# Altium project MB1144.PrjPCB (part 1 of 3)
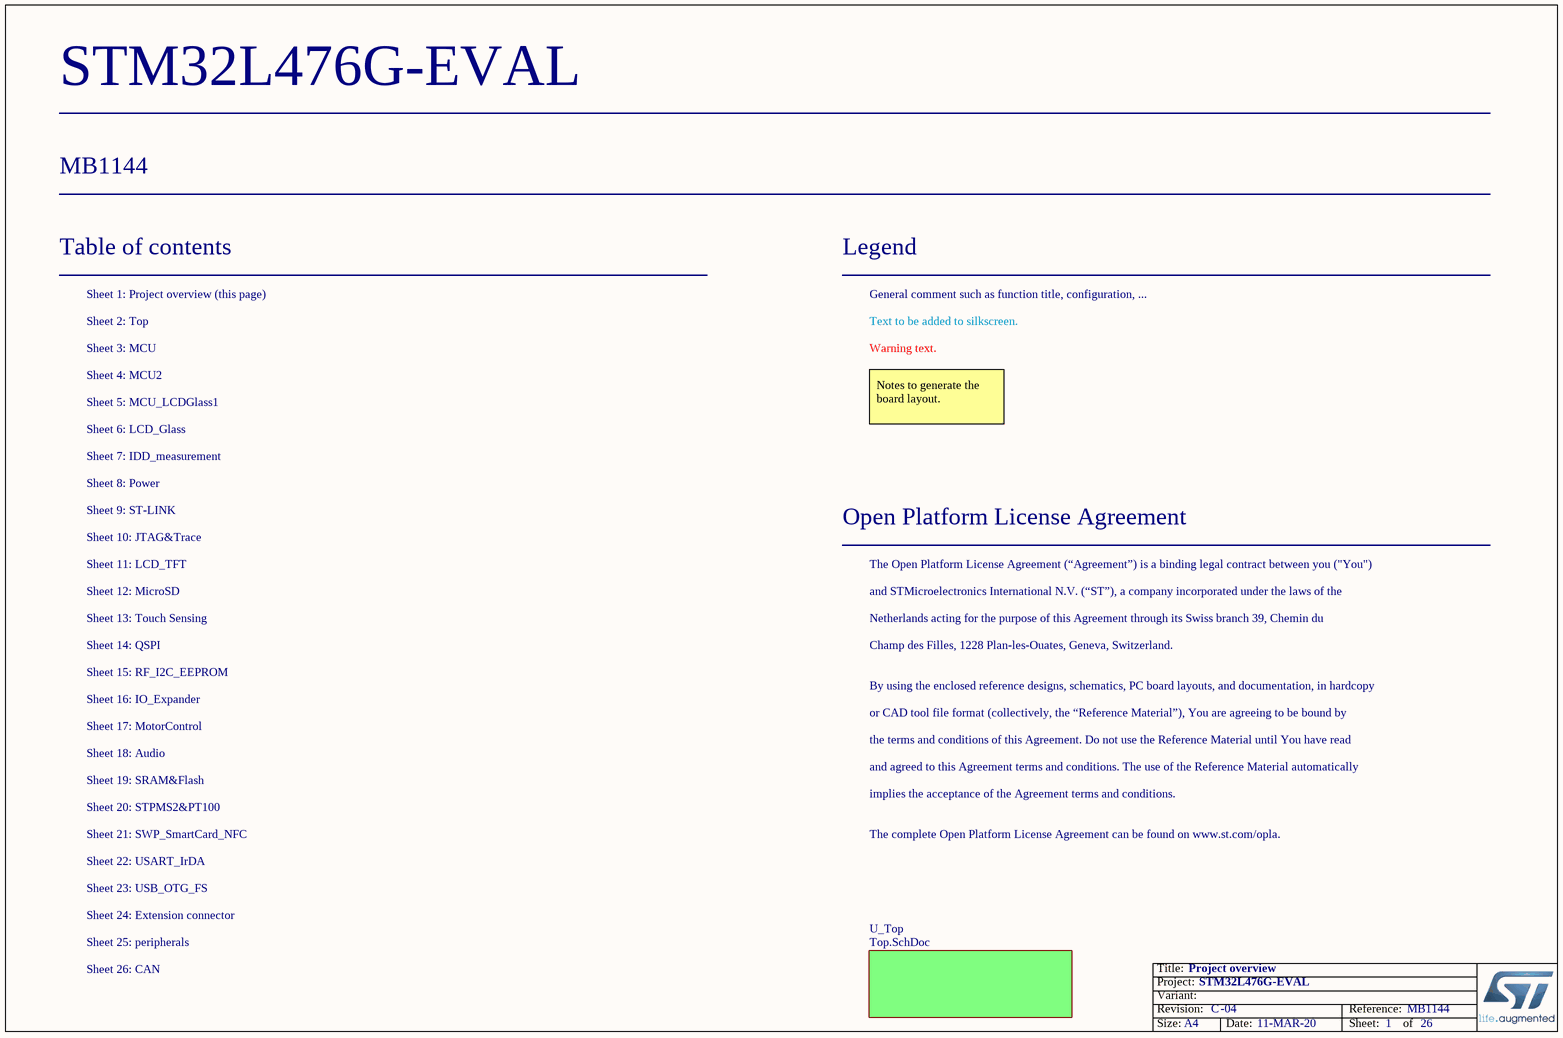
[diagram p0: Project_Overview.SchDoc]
Board_Assembly_Revision: 04; Board_Document_Date: 11-MAR-20; Board_Name: STM32L476G-EVAL; Board_PCB_Revision: C; Board_Reference: MB1144
26 sheets, 601 parts. Net scope: flat (ports and power ports of the same name join across sheets).
Sheets:
  Project_Overview.SchDoc
    U_Top = Top.SchDoc
      U_MCU_LCDGlass_Symbol = MCU_LCDGlass_Symbol.SchDoc
        U_MCU = MCU.SchDoc
        U_LCD_Glass = LCD_Glass.SchDoc
        U_IO_Expandor = IO_Expandor.SchDoc
        U_MCU2 = MCU2.SchDoc
      U_SRAM&Flash = SRAM&Flash.SchDoc
      U_MotorControl = MotorControl.SchDoc
      U_MicroSD = MicroSD.SchDoc
      U_QSPI = QSPI.SchDoc
      U_Extension connector = Extension connector.SCHDOC
      U_JTAG&Trace = JTAG&Trace.SchDoc
      U_ST_LINK = ST_LINK.SCHDOC
      U_USART_IrDA = USART_IrDA.SchDoc
      U_SWP_SmartCard_NFC = SWP_SmartCard_NFC.SchDoc
      U_STPMS2&PT100 = STPMS2&PT100.SchDoc
      U_IDD_measurement = IDD_measurement.SchDoc
      U_USB_OTG_FS = USB_OTG_FS.SchDoc
      U_Touch Sensing = Touch Sensing.SchDoc
      U_CAN = CAN.SchDoc
      U_peripherals = peripherals.SchDoc
      U_Power = Power.SchDoc
      U_Audio = Audio.SchDoc
      U_LCD_TFT = LCD_TFT.SchDoc
      U_RF_I2C_EEPROM = RF_I2C_EEPROM.SchDoc

## Sheet Project_Overview.SchDoc: Project overview
size A4; Date: Not used; ApprovedBy: Not used; CheckedBy: Not used; Author: Not used; CompanyName: STMicroelectronics; DrawnBy: Not used; Engineer: Not used; Organization: Not used; Address1: Not used; Address2: Not used; Address3: Not used; Address4: Not used; DocumentNumber: 1; Revision: Not used; SheetNumber: 1; SheetTotal: 26

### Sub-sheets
U_Top = Top.SchDoc: no entries

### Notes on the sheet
- Table of contents
- Sheet 1: Project overview (this page)
- Legend
- General comment such as function title, configuration, ...
- Sheet 2: Top
- Sheet 3: MCU
- Sheet 4: MCU2
- Text to be added to silkscreen.
- Warning text.
- Sheet 5: MCU_LCDGlass1
- Sheet 6: LCD_Glass
- Notes to generate the board layout.
- Sheet 7: IDD_measurement
- Sheet 8: Power
- Sheet 9: ST-LINK
- Sheet 10: JTAG&Trace
- Sheet 11: LCD_TFT
- Open Platform License Agreement
- The Open Platform License Agreement (“Agreement”) is a binding legal contract between you ("You")
- Sheet 12: MicroSD
- Sheet 13: Touch Sensing
- Sheet 14: QSPI
- and STMicroelectronics International N.V. (“ST”), a company incorporated under the laws of the
- Netherlands acting for the purpose of this Agreement through its Swiss branch 39, Chemin du
- Champ des Filles, 1228 Plan-les-Ouates, Geneva, Switzerland.
- Sheet 15: RF_I2C_EEPROM
- Sheet 16: IO_Expander
- By using the enclosed reference designs, schematics, PC board layouts, and documentation, in hardcopy
- or CAD tool file format (collectively, the “Reference Material”), You are agreeing to be bound by
- Sheet 17: MotorControl
- Sheet 18: Audio
- Sheet 19: SRAM&Flash
- the terms and conditions of this Agreement. Do not use the Reference Material until You have read
- and agreed to this Agreement terms and conditions. The use of the Reference Material automatically
- Sheet 20: STPMS2&PT100
- Sheet 21: SWP_SmartCard_NFC
- implies the acceptance of the Agreement terms and conditions.
- The complete Open Platform License Agreement can be found on www.st.com/opla.
- Sheet 22: USART_IrDA
- Sheet 23: USB_OTG_FS
- Sheet 24: Extension connector
- Sheet 25: peripherals
- Sheet 26: CAN

## Sheet Top.SchDoc: Top schematic
size A3; DocumentNumber: 2; Revision: C-02; SheetNumber: 2; SheetTotal: 26; PageSetup: Record=PageOptions¦CenterHorizontal=True¦CenterVertical=True¦PrintScale=1.01¦XCorrection=1.00¦YCorrection=1.00¦PrintKind=1¦BorderSize=5000000¦LeftOffset=0¦BottomOffset=0¦Orientation=2¦PaperLength=1000¦PaperWidth=1000¦Scale=100¦PaperSource=264¦PrintQuality=600¦MediaType=1¦DitherType=10¦PaperKind=A3¦PrintScaleMode=1; Project: STM32L476G-EVAL
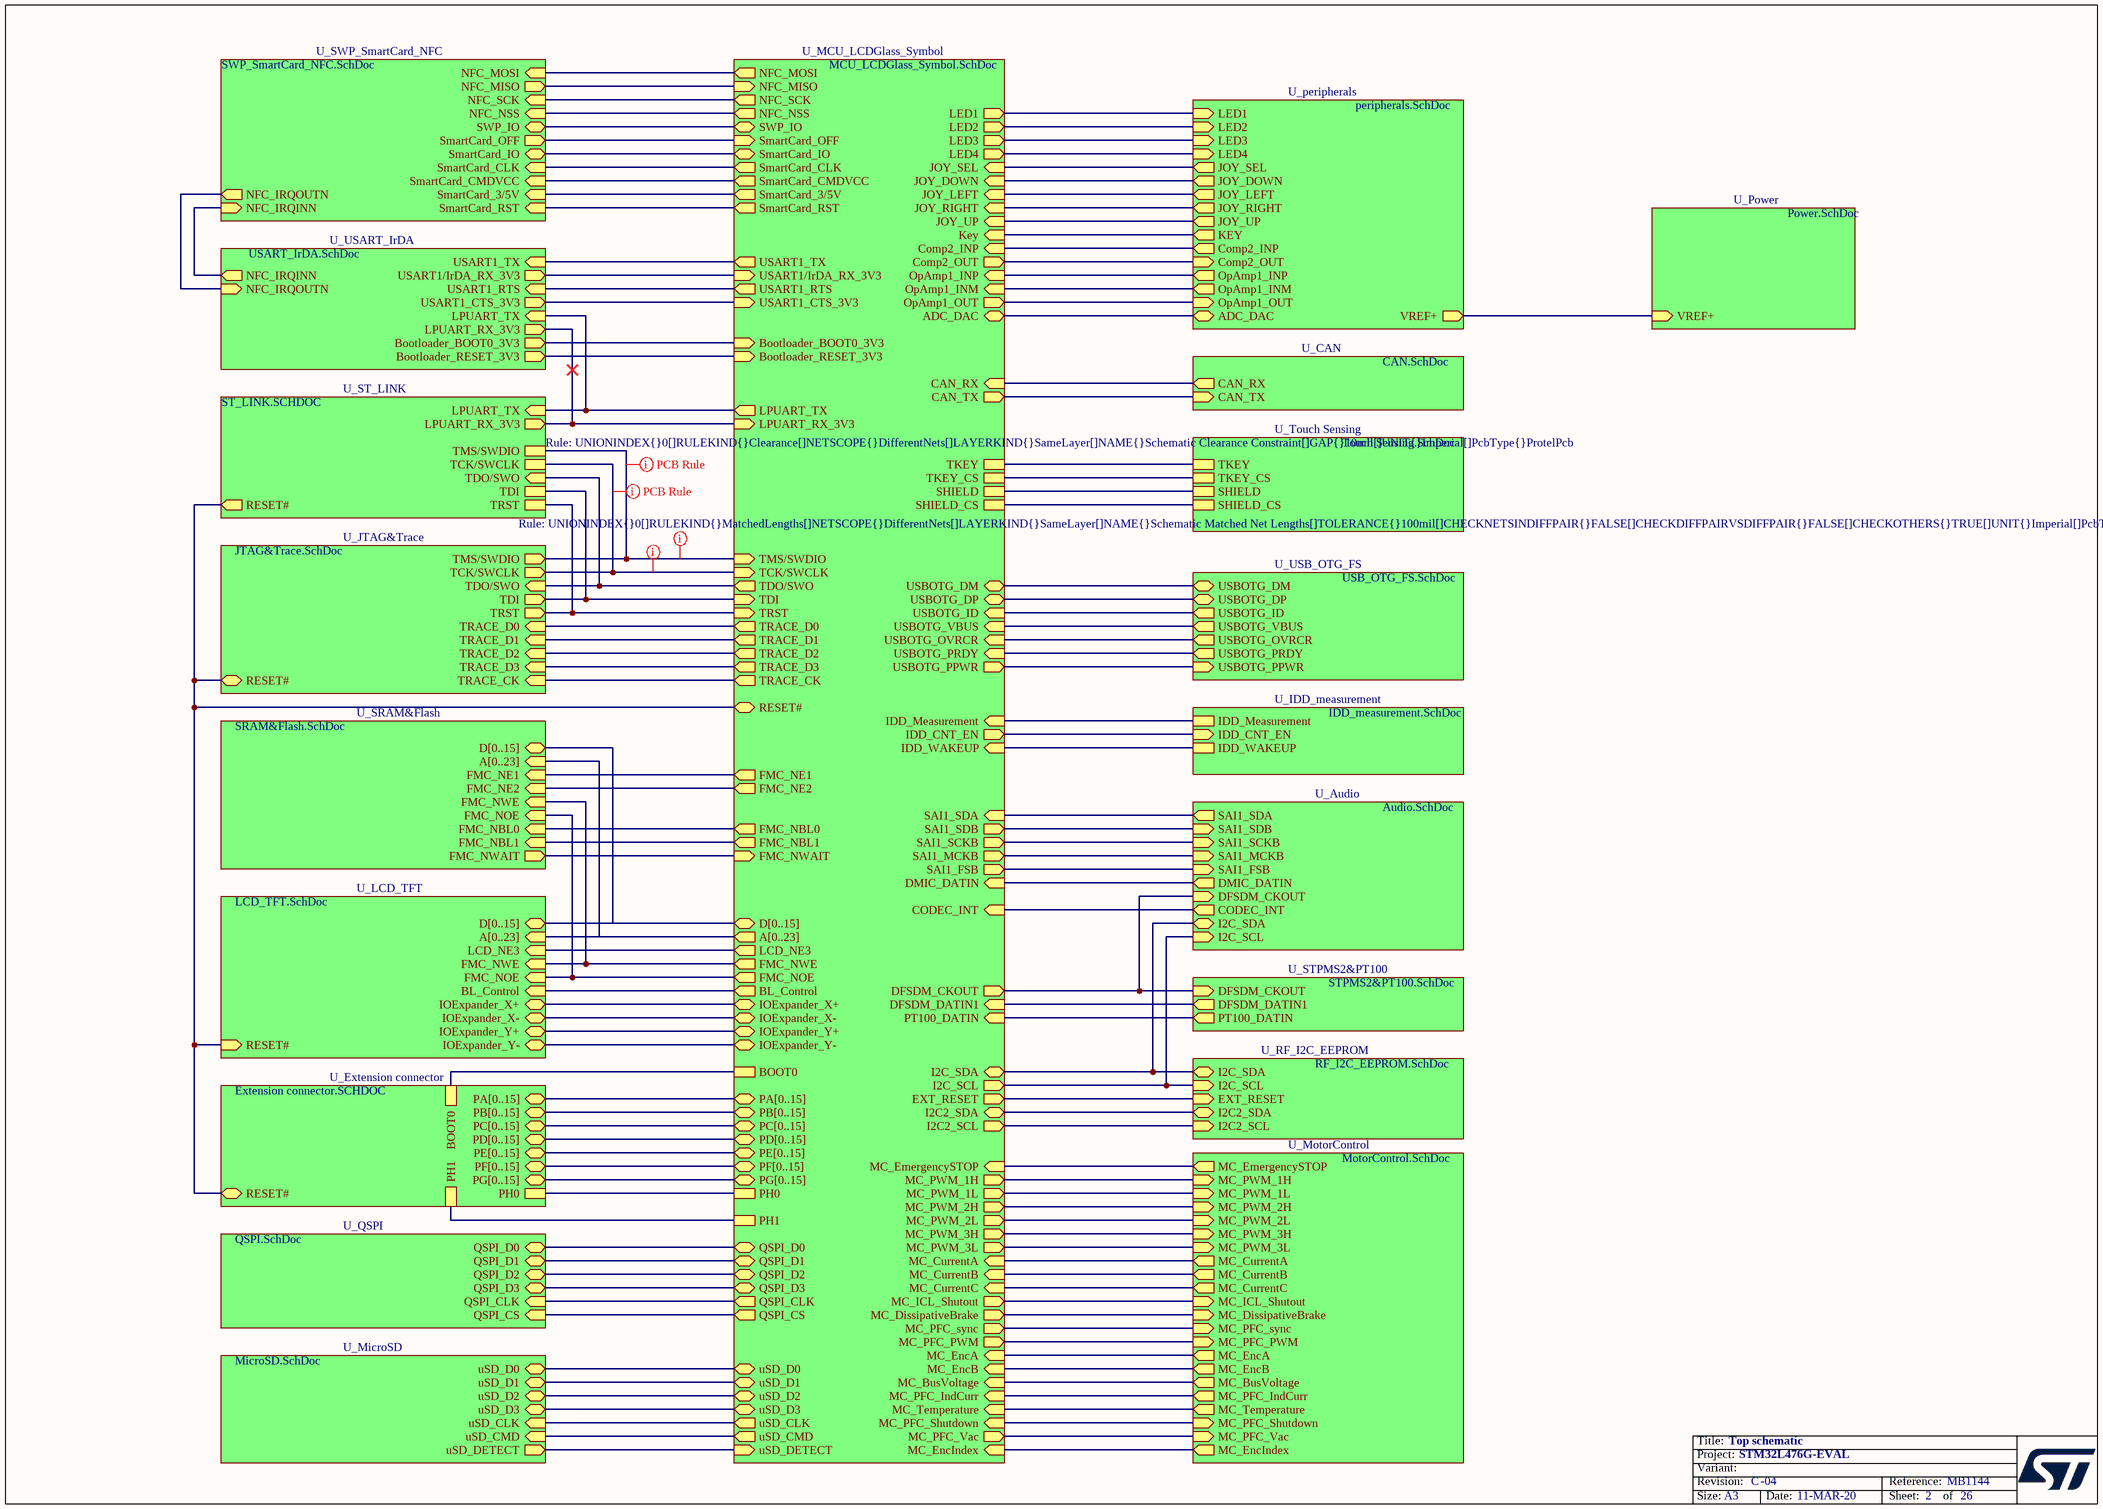
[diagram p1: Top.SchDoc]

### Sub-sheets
U_Audio = Audio.SchDoc: SAI1_SCKB (in), SAI1_FSB (in), SAI1_SDB (in), CODEC_INT (out), I2C_SCL (in), SAI1_MCKB (in), I2C_SDA (bidir), DMIC_DATIN (out), DFSDM_CKOUT (in), SAI1_SDA (out)
U_CAN = CAN.SchDoc: CAN_TX (in), CAN_RX (out)
U_Extension connector = Extension connector.SCHDOC: PA[0..15] (bidir), PB[0..15] (bidir), PC[0..15] (bidir), PD[0..15] (bidir), PE[0..15] (bidir), RESET# (bidir), PF[0..15] (bidir), PG[0..15] (bidir), PH1, PH0, BOOT0
U_IDD_measurement = IDD_measurement.SchDoc: IDD_Measurement, IDD_CNT_EN (in), IDD_WAKEUP
U_JTAG&Trace = JTAG&Trace.SchDoc: TDI (out), RESET# (bidir), TRACE_D3 (in), TRACE_D2 (in), TRACE_D1 (in), TRACE_D0 (in), TRACE_CK (in), TRST (out), TMS/SWDIO (out), TCK/SWCLK (out), TDO/SWO (in)
U_LCD_TFT = LCD_TFT.SchDoc: RESET# (in), FMC_NWE (in), LCD_NE3 (in), FMC_NOE (in), D[0..15] (bidir), A[0..23] (in), IOExpander_Y+ (bidir), IOExpander_Y- (bidir), IOExpander_X+ (bidir), IOExpander_X- (bidir), BL_Control (in)
U_MCU_LCDGlass_Symbol = MCU_LCDGlass_Symbol.SchDoc: FMC_NWAIT (in), FMC_NOE (out), FMC_NWE (out), FMC_NE1 (out), FMC_NE2 (out), LCD_NE3 (out), LED1 (out), LED2 (out), LPUART_TX (out), USART1_TX (out), USART1_RTS (out), TMS/SWDIO (in), TCK/SWCLK (in), TDI (in), TRST (in), Key (in), DFSDM_DATIN1 (in), IDD_Measurement (in), CODEC_INT (in), USBOTG_PRDY (in), USBOTG_OVRCR (in), DMIC_DATIN (in), PT100_DATIN (in), USBOTG_VBUS (in), USBOTG_ID (in), IDD_WAKEUP (in), OpAmp1_INM (in), Comp2_INP (in), TDO/SWO (out), TRACE_D1 (out), TRACE_D2 (out), TRACE_D3 (out), IDD_CNT_EN (out), USBOTG_PPWR (out), TRACE_CK (out), TRACE_D0 (out), SmartCard_CLK (out), OpAmp1_OUT (out), ADC_DAC (bidir), USBOTG_DP (bidir), USBOTG_DM (bidir), SmartCard_IO (bidir), QSPI_D0 (bidir), QSPI_D1 (bidir), QSPI_D2 (bidir), QSPI_D3 (bidir), uSD_D0 (bidir), uSD_D1 (bidir), uSD_D2 (bidir), uSD_D3 (bidir), MC_DissipativeBrake (out), MC_PFC_sync (out), MC_PWM_1H (out), MC_PWM_1L (out), MC_PWM_2H (out), MC_PWM_2L (out), MC_PWM_3H (out), MC_PWM_3L (out), MC_ICL_Shutout (out), MC_PFC_PWM (out), MC_PFC_Vac (out), QSPI_CLK (out), QSPI_CS (out), FMC_NBL0 (out), FMC_NBL1 (out), CAN_TX (out), MC_EncA (in), MC_EncB (in), MC_EncIndex (in), MC_CurrentB (in), MC_CurrentC (in), MC_Temperature (in), MC_PFC_Shutdown (in), CAN_RX (in), uSD_DETECT (in), uSD_CMD (out), uSD_CLK (out), SWP_IO (bidir), IOExpander_X+ (bidir), IOExpander_X- (bidir), IOExpander_Y+ (bidir), IOExpander_Y- (bidir), JOY_SEL (in), JOY_DOWN (in), JOY_LEFT (in), JOY_RIGHT (in), JOY_UP (in), SmartCard_OFF (in), LED4 (out), LED3 (out), SmartCard_RST (out), SmartCard_CMDVCC (out), SmartCard_3/5V (out), D[0..15] (bidir), A[0..23] (out), PA[0..15] (bidir), PB[0..15] (bidir), PC[0..15] (bidir), PD[0..15] (bidir), PE[0..15] (bidir), PF[0..15] (bidir), PG[0..15] (bidir), MC_CurrentA (in), MC_EmergencySTOP (in), MC_BusVoltage (in), MC_PFC_IndCurr (in), RESET# (bidir), DFSDM_CKOUT (out), I2C_SCL (out), I2C_SDA (bidir), PH1, PH0, SHIELD, SAI1_MCKB (out), SAI1_SCKB (out), SAI1_FSB (out), SAI1_SDB (out), SAI1_SDA (in), OpAmp1_INP (in), Comp2_OUT (out), TKEY, TKEY_CS, SHIELD_CS, Bootloader_RESET_3V3 (in), Bootloader_BOOT0_3V3 (in), LPUART_RX_3V3 (in), USART1_CTS_3V3 (in), USART1/IrDA_RX_3V3 (in), BL_Control (out), EXT_RESET (out), BOOT0, NFC_NSS (out), NFC_MOSI (out), NFC_SCK (out), NFC_MISO (in), I2C2_SDA (bidir), I2C2_SCL (out)
U_MicroSD = MicroSD.SchDoc: uSD_CLK (in), uSD_CMD (in), uSD_D0 (bidir), uSD_D1 (bidir), uSD_D2 (bidir), uSD_D3 (bidir), uSD_DETECT (out)
U_MotorControl = MotorControl.SchDoc: MC_EmergencySTOP (out), MC_CurrentA (out), MC_CurrentB (out), MC_CurrentC (out), MC_PFC_sync (in), MC_PWM_3L (in), MC_PWM_2H (in), MC_PWM_2L (in), MC_PWM_1H (in), MC_PWM_1L (in), MC_PWM_3H (in), MC_ICL_Shutout (in), MC_DissipativeBrake (in), MC_PFC_PWM (in), MC_EncA (out), MC_EncB (out), MC_BusVoltage (out), MC_EncIndex (out), MC_PFC_IndCurr (out), MC_Temperature (out), MC_PFC_Shutdown (in), MC_PFC_Vac (in)
U_peripherals = peripherals.SchDoc: ADC_DAC (bidir), LED4 (in), LED3 (in), LED1 (in), LED2 (in), JOY_SEL (out), JOY_DOWN (out), JOY_LEFT (out), JOY_RIGHT (out), JOY_UP (out), KEY (out), VREF+ (out), Comp2_INP (out), OpAmp1_OUT (in), OpAmp1_INM (out), OpAmp1_INP (out), Comp2_OUT (in)
U_Power = Power.SchDoc: VREF+ (in)
U_QSPI = QSPI.SchDoc: QSPI_D0 (bidir), QSPI_D3 (bidir), QSPI_D2 (bidir), QSPI_D1 (bidir), QSPI_CLK (in), QSPI_CS (in)
U_RF_I2C_EEPROM = RF_I2C_EEPROM.SchDoc: I2C_SCL (in), I2C_SDA (bidir), EXT_RESET (in), I2C2_SDA (bidir), I2C2_SCL (in)
U_SRAM&Flash = SRAM&Flash.SchDoc: FMC_NWE (in), FMC_NOE (in), FMC_NWAIT (out), FMC_NBL0 (in), FMC_NBL1 (in), D[0..15] (bidir), A[0..23] (in), FMC_NE1 (in), FMC_NE2 (in)
U_ST_LINK = ST_LINK.SCHDOC: TDO/SWO (in), RESET# (out), TDI, TRST, TMS/SWDIO, TCK/SWCLK, LPUART_RX_3V3 (out), LPUART_TX (in)
U_STPMS2&PT100 = STPMS2&PT100.SchDoc: DFSDM_CKOUT (in), DFSDM_DATIN1 (out), PT100_DATIN (out)
U_SWP_SmartCard_NFC = SWP_SmartCard_NFC.SchDoc: SWP_IO (bidir), SmartCard_3/5V (in), SmartCard_IO (bidir), SmartCard_RST (in), SmartCard_CLK (in), SmartCard_OFF (out), SmartCard_CMDVCC (in), NFC_IRQINN (in), NFC_IRQOUTN (out), NFC_NSS (in), NFC_MOSI (in), NFC_MISO (out), NFC_SCK (in)
U_Touch Sensing = Touch Sensing.SchDoc: SHIELD, SHIELD_CS, TKEY_CS, TKEY
U_USART_IrDA = USART_IrDA.SchDoc: USART1/IrDA_RX_3V3 (out), Bootloader_BOOT0_3V3 (out), Bootloader_RESET_3V3 (out), USART1_CTS_3V3 (out), USART1_TX (in), USART1_RTS (in), LPUART_RX_3V3 (out), LPUART_TX (in), NFC_IRQINN (out), NFC_IRQOUTN (in)
U_USB_OTG_FS = USB_OTG_FS.SchDoc: USBOTG_VBUS (out), USBOTG_PRDY (out), USBOTG_DM (bidir), USBOTG_DP (bidir), USBOTG_OVRCR (out), USBOTG_PPWR (in), USBOTG_ID (out)

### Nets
(unnamed): sheet U_MCU_LCDGlass_Symbol/FMC_NWAIT, sheet U_SRAM&Flash/FMC_NWAIT
(unnamed): sheet U_MCU_LCDGlass_Symbol/FMC_NOE, sheet U_SRAM&Flash/FMC_NOE, sheet U_LCD_TFT/FMC_NOE  [a separate net that carries the same name]
(unnamed): sheet U_MCU_LCDGlass_Symbol/FMC_NWE, sheet U_SRAM&Flash/FMC_NWE, sheet U_LCD_TFT/FMC_NWE  [a separate net that carries the same name]
(unnamed): sheet U_MCU_LCDGlass_Symbol/FMC_NE1, sheet U_SRAM&Flash/FMC_NE1  [a separate net that carries the same name]
(unnamed): sheet U_MCU_LCDGlass_Symbol/FMC_NE2, sheet U_SRAM&Flash/FMC_NE2  [a separate net that carries the same name]
(unnamed): sheet U_MCU_LCDGlass_Symbol/LCD_NE3, sheet U_LCD_TFT/LCD_NE3  [a separate net that carries the same name]
(unnamed): sheet U_MCU_LCDGlass_Symbol/LED1, sheet U_peripherals/LED1  [a separate net that carries the same name]
(unnamed): sheet U_MCU_LCDGlass_Symbol/LED2, sheet U_peripherals/LED2  [a separate net that carries the same name]
(unnamed): sheet U_MCU_LCDGlass_Symbol/LPUART_TX, sheet U_ST_LINK/LPUART_TX, sheet U_USART_IrDA/LPUART_TX  [a separate net that carries the same name]
(unnamed): sheet U_MCU_LCDGlass_Symbol/USART1_TX, sheet U_USART_IrDA/USART1_TX  [a separate net that carries the same name]
(unnamed): sheet U_MCU_LCDGlass_Symbol/USART1_RTS, sheet U_USART_IrDA/USART1_RTS  [a separate net that carries the same name]
(unnamed): sheet U_MCU_LCDGlass_Symbol/TMS/SWDIO, sheet U_JTAG&Trace/TMS/SWDIO, sheet U_ST_LINK/TMS/SWDIO  [a separate net that carries the same name]
(unnamed): sheet U_MCU_LCDGlass_Symbol/TCK/SWCLK, sheet U_JTAG&Trace/TCK/SWCLK, sheet U_ST_LINK/TCK/SWCLK  [a separate net that carries the same name]
(unnamed): sheet U_MCU_LCDGlass_Symbol/TDI, sheet U_JTAG&Trace/TDI, sheet U_ST_LINK/TDI  [a separate net that carries the same name]
(unnamed): sheet U_MCU_LCDGlass_Symbol/TRST, sheet U_JTAG&Trace/TRST, sheet U_ST_LINK/TRST  [a separate net that carries the same name]
(unnamed): sheet U_MCU_LCDGlass_Symbol/Key, sheet U_peripherals/KEY  [a separate net that carries the same name]
(unnamed): sheet U_MCU_LCDGlass_Symbol/DFSDM_DATIN1, sheet U_STPMS2&PT100/DFSDM_DATIN1  [a separate net that carries the same name]
(unnamed): sheet U_MCU_LCDGlass_Symbol/IDD_Measurement, sheet U_IDD_measurement/IDD_Measurement  [a separate net that carries the same name]
(unnamed): sheet U_MCU_LCDGlass_Symbol/CODEC_INT, sheet U_Audio/CODEC_INT  [a separate net that carries the same name]
(unnamed): sheet U_MCU_LCDGlass_Symbol/USBOTG_PRDY, sheet U_USB_OTG_FS/USBOTG_PRDY  [a separate net that carries the same name]
(unnamed): sheet U_MCU_LCDGlass_Symbol/USBOTG_OVRCR, sheet U_USB_OTG_FS/USBOTG_OVRCR  [a separate net that carries the same name]
(unnamed): sheet U_MCU_LCDGlass_Symbol/DMIC_DATIN, sheet U_Audio/DMIC_DATIN  [a separate net that carries the same name]
(unnamed): sheet U_MCU_LCDGlass_Symbol/PT100_DATIN, sheet U_STPMS2&PT100/PT100_DATIN  [a separate net that carries the same name]
(unnamed): sheet U_MCU_LCDGlass_Symbol/USBOTG_VBUS, sheet U_USB_OTG_FS/USBOTG_VBUS  [a separate net that carries the same name]
(unnamed): sheet U_MCU_LCDGlass_Symbol/USBOTG_ID, sheet U_USB_OTG_FS/USBOTG_ID  [a separate net that carries the same name]
(unnamed): sheet U_MCU_LCDGlass_Symbol/IDD_WAKEUP, sheet U_IDD_measurement/IDD_WAKEUP  [a separate net that carries the same name]
(unnamed): sheet U_MCU_LCDGlass_Symbol/OpAmp1_INM, sheet U_peripherals/OpAmp1_INM  [a separate net that carries the same name]
(unnamed): sheet U_MCU_LCDGlass_Symbol/Comp2_INP, sheet U_peripherals/Comp2_INP  [a separate net that carries the same name]
(unnamed): sheet U_MCU_LCDGlass_Symbol/TDO/SWO, sheet U_JTAG&Trace/TDO/SWO, sheet U_ST_LINK/TDO/SWO  [a separate net that carries the same name]
(unnamed): sheet U_MCU_LCDGlass_Symbol/TRACE_D1, sheet U_JTAG&Trace/TRACE_D1  [a separate net that carries the same name]
(unnamed): sheet U_MCU_LCDGlass_Symbol/TRACE_D2, sheet U_JTAG&Trace/TRACE_D2  [a separate net that carries the same name]
(unnamed): sheet U_MCU_LCDGlass_Symbol/TRACE_D3, sheet U_JTAG&Trace/TRACE_D3  [a separate net that carries the same name]
(unnamed): sheet U_MCU_LCDGlass_Symbol/IDD_CNT_EN, sheet U_IDD_measurement/IDD_CNT_EN  [a separate net that carries the same name]
(unnamed): sheet U_MCU_LCDGlass_Symbol/USBOTG_PPWR, sheet U_USB_OTG_FS/USBOTG_PPWR  [a separate net that carries the same name]
(unnamed): sheet U_MCU_LCDGlass_Symbol/TRACE_CK, sheet U_JTAG&Trace/TRACE_CK  [a separate net that carries the same name]
(unnamed): sheet U_MCU_LCDGlass_Symbol/TRACE_D0, sheet U_JTAG&Trace/TRACE_D0  [a separate net that carries the same name]
(unnamed): sheet U_MCU_LCDGlass_Symbol/SmartCard_CLK, sheet U_SWP_SmartCard_NFC/SmartCard_CLK  [a separate net that carries the same name]
(unnamed): sheet U_MCU_LCDGlass_Symbol/OpAmp1_OUT, sheet U_peripherals/OpAmp1_OUT  [a separate net that carries the same name]
(unnamed): sheet U_MCU_LCDGlass_Symbol/ADC_DAC, sheet U_peripherals/ADC_DAC  [a separate net that carries the same name]
(unnamed): sheet U_MCU_LCDGlass_Symbol/USBOTG_DP, sheet U_USB_OTG_FS/USBOTG_DP  [a separate net that carries the same name]
(unnamed): sheet U_MCU_LCDGlass_Symbol/USBOTG_DM, sheet U_USB_OTG_FS/USBOTG_DM  [a separate net that carries the same name]
(unnamed): sheet U_MCU_LCDGlass_Symbol/SmartCard_IO, sheet U_SWP_SmartCard_NFC/SmartCard_IO  [a separate net that carries the same name]
(unnamed): sheet U_MCU_LCDGlass_Symbol/QSPI_D0, sheet U_QSPI/QSPI_D0  [a separate net that carries the same name]
(unnamed): sheet U_MCU_LCDGlass_Symbol/QSPI_D1, sheet U_QSPI/QSPI_D1  [a separate net that carries the same name]
(unnamed): sheet U_MCU_LCDGlass_Symbol/QSPI_D2, sheet U_QSPI/QSPI_D2  [a separate net that carries the same name]
(unnamed): sheet U_MCU_LCDGlass_Symbol/QSPI_D3, sheet U_QSPI/QSPI_D3  [a separate net that carries the same name]
(unnamed): sheet U_MCU_LCDGlass_Symbol/uSD_D0, sheet U_MicroSD/uSD_D0  [a separate net that carries the same name]
(unnamed): sheet U_MCU_LCDGlass_Symbol/uSD_D1, sheet U_MicroSD/uSD_D1  [a separate net that carries the same name]
(unnamed): sheet U_MCU_LCDGlass_Symbol/uSD_D2, sheet U_MicroSD/uSD_D2  [a separate net that carries the same name]
(unnamed): sheet U_MCU_LCDGlass_Symbol/uSD_D3, sheet U_MicroSD/uSD_D3  [a separate net that carries the same name]
(unnamed): sheet U_MCU_LCDGlass_Symbol/MC_DissipativeBrake, sheet U_MotorControl/MC_DissipativeBrake  [a separate net that carries the same name]
(unnamed): sheet U_MCU_LCDGlass_Symbol/MC_PFC_sync, sheet U_MotorControl/MC_PFC_sync  [a separate net that carries the same name]
(unnamed): sheet U_MCU_LCDGlass_Symbol/MC_PWM_1H, sheet U_MotorControl/MC_PWM_1H  [a separate net that carries the same name]
(unnamed): sheet U_MCU_LCDGlass_Symbol/MC_PWM_1L, sheet U_MotorControl/MC_PWM_1L  [a separate net that carries the same name]
(unnamed): sheet U_MCU_LCDGlass_Symbol/MC_PWM_2H, sheet U_MotorControl/MC_PWM_2H  [a separate net that carries the same name]
(unnamed): sheet U_MCU_LCDGlass_Symbol/MC_PWM_2L, sheet U_MotorControl/MC_PWM_2L  [a separate net that carries the same name]
(unnamed): sheet U_MCU_LCDGlass_Symbol/MC_PWM_3H, sheet U_MotorControl/MC_PWM_3H  [a separate net that carries the same name]
(unnamed): sheet U_MCU_LCDGlass_Symbol/MC_PWM_3L, sheet U_MotorControl/MC_PWM_3L  [a separate net that carries the same name]
(unnamed): sheet U_MCU_LCDGlass_Symbol/MC_ICL_Shutout, sheet U_MotorControl/MC_ICL_Shutout  [a separate net that carries the same name]
(unnamed): sheet U_MCU_LCDGlass_Symbol/MC_PFC_PWM, sheet U_MotorControl/MC_PFC_PWM  [a separate net that carries the same name]
(unnamed): sheet U_MCU_LCDGlass_Symbol/MC_PFC_Vac, sheet U_MotorControl/MC_PFC_Vac  [a separate net that carries the same name]
(unnamed): sheet U_MCU_LCDGlass_Symbol/QSPI_CLK, sheet U_QSPI/QSPI_CLK  [a separate net that carries the same name]
(unnamed): sheet U_MCU_LCDGlass_Symbol/QSPI_CS, sheet U_QSPI/QSPI_CS  [a separate net that carries the same name]
(unnamed): sheet U_MCU_LCDGlass_Symbol/FMC_NBL0, sheet U_SRAM&Flash/FMC_NBL0  [a separate net that carries the same name]
(unnamed): sheet U_MCU_LCDGlass_Symbol/FMC_NBL1, sheet U_SRAM&Flash/FMC_NBL1  [a separate net that carries the same name]
(unnamed): sheet U_MCU_LCDGlass_Symbol/CAN_TX, sheet U_CAN/CAN_TX  [a separate net that carries the same name]
(unnamed): sheet U_MCU_LCDGlass_Symbol/MC_EncA, sheet U_MotorControl/MC_EncA  [a separate net that carries the same name]
(unnamed): sheet U_MCU_LCDGlass_Symbol/MC_EncB, sheet U_MotorControl/MC_EncB  [a separate net that carries the same name]
(unnamed): sheet U_MCU_LCDGlass_Symbol/MC_EncIndex, sheet U_MotorControl/MC_EncIndex  [a separate net that carries the same name]
(unnamed): sheet U_MCU_LCDGlass_Symbol/MC_CurrentB, sheet U_MotorControl/MC_CurrentB  [a separate net that carries the same name]
(unnamed): sheet U_MCU_LCDGlass_Symbol/MC_CurrentC, sheet U_MotorControl/MC_CurrentC  [a separate net that carries the same name]
(unnamed): sheet U_MCU_LCDGlass_Symbol/MC_Temperature, sheet U_MotorControl/MC_Temperature  [a separate net that carries the same name]
(unnamed): sheet U_MCU_LCDGlass_Symbol/MC_PFC_Shutdown, sheet U_MotorControl/MC_PFC_Shutdown  [a separate net that carries the same name]
(unnamed): sheet U_MCU_LCDGlass_Symbol/CAN_RX, sheet U_CAN/CAN_RX  [a separate net that carries the same name]
(unnamed): sheet U_MCU_LCDGlass_Symbol/uSD_DETECT, sheet U_MicroSD/uSD_DETECT  [a separate net that carries the same name]
(unnamed): sheet U_MCU_LCDGlass_Symbol/uSD_CMD, sheet U_MicroSD/uSD_CMD  [a separate net that carries the same name]
(unnamed): sheet U_MCU_LCDGlass_Symbol/uSD_CLK, sheet U_MicroSD/uSD_CLK  [a separate net that carries the same name]
(unnamed): sheet U_MCU_LCDGlass_Symbol/SWP_IO, sheet U_SWP_SmartCard_NFC/SWP_IO  [a separate net that carries the same name]
(unnamed): sheet U_MCU_LCDGlass_Symbol/IOExpander_X+, sheet U_LCD_TFT/IOExpander_X+  [a separate net that carries the same name]
(unnamed): sheet U_MCU_LCDGlass_Symbol/IOExpander_X-, sheet U_LCD_TFT/IOExpander_X-  [a separate net that carries the same name]
(unnamed): sheet U_MCU_LCDGlass_Symbol/IOExpander_Y+, sheet U_LCD_TFT/IOExpander_Y+  [a separate net that carries the same name]
(unnamed): sheet U_MCU_LCDGlass_Symbol/IOExpander_Y-, sheet U_LCD_TFT/IOExpander_Y-  [a separate net that carries the same name]
(unnamed): sheet U_MCU_LCDGlass_Symbol/JOY_SEL, sheet U_peripherals/JOY_SEL  [a separate net that carries the same name]
(unnamed): sheet U_MCU_LCDGlass_Symbol/JOY_DOWN, sheet U_peripherals/JOY_DOWN  [a separate net that carries the same name]
(unnamed): sheet U_MCU_LCDGlass_Symbol/JOY_LEFT, sheet U_peripherals/JOY_LEFT  [a separate net that carries the same name]
(unnamed): sheet U_MCU_LCDGlass_Symbol/JOY_RIGHT, sheet U_peripherals/JOY_RIGHT  [a separate net that carries the same name]
(unnamed): sheet U_MCU_LCDGlass_Symbol/JOY_UP, sheet U_peripherals/JOY_UP  [a separate net that carries the same name]
(unnamed): sheet U_MCU_LCDGlass_Symbol/SmartCard_OFF, sheet U_SWP_SmartCard_NFC/SmartCard_OFF  [a separate net that carries the same name]
(unnamed): sheet U_MCU_LCDGlass_Symbol/LED4, sheet U_peripherals/LED4  [a separate net that carries the same name]
(unnamed): sheet U_MCU_LCDGlass_Symbol/LED3, sheet U_peripherals/LED3  [a separate net that carries the same name]
(unnamed): sheet U_MCU_LCDGlass_Symbol/SmartCard_RST, sheet U_SWP_SmartCard_NFC/SmartCard_RST  [a separate net that carries the same name]
(unnamed): sheet U_MCU_LCDGlass_Symbol/SmartCard_CMDVCC, sheet U_SWP_SmartCard_NFC/SmartCard_CMDVCC  [a separate net that carries the same name]
(unnamed): sheet U_MCU_LCDGlass_Symbol/SmartCard_3/5V, sheet U_SWP_SmartCard_NFC/SmartCard_3/5V  [a separate net that carries the same name]
(unnamed): sheet U_MCU_LCDGlass_Symbol/MC_CurrentA, sheet U_MotorControl/MC_CurrentA  [a separate net that carries the same name]
(unnamed): sheet U_MCU_LCDGlass_Symbol/MC_EmergencySTOP, sheet U_MotorControl/MC_EmergencySTOP  [a separate net that carries the same name]
(unnamed): sheet U_MCU_LCDGlass_Symbol/MC_BusVoltage, sheet U_MotorControl/MC_BusVoltage  [a separate net that carries the same name]
(unnamed): sheet U_MCU_LCDGlass_Symbol/MC_PFC_IndCurr, sheet U_MotorControl/MC_PFC_IndCurr  [a separate net that carries the same name]
(unnamed): sheet U_MCU_LCDGlass_Symbol/RESET#, sheet U_Extension connector/RESET#, sheet U_JTAG&Trace/RESET#, sheet U_ST_LINK/RESET#, sheet U_LCD_TFT/RESET#  [a separate net that carries the same name]
(unnamed): sheet U_MCU_LCDGlass_Symbol/DFSDM_CKOUT, sheet U_STPMS2&PT100/DFSDM_CKOUT, sheet U_Audio/DFSDM_CKOUT  [a separate net that carries the same name]
(unnamed): sheet U_MCU_LCDGlass_Symbol/I2C_SCL, sheet U_Audio/I2C_SCL, sheet U_RF_I2C_EEPROM/I2C_SCL  [a separate net that carries the same name]
(unnamed): sheet U_MCU_LCDGlass_Symbol/I2C_SDA, sheet U_Audio/I2C_SDA, sheet U_RF_I2C_EEPROM/I2C_SDA  [a separate net that carries the same name]
(unnamed): sheet U_MCU_LCDGlass_Symbol/PH1, sheet U_Extension connector/PH1  [a separate net that carries the same name]
(unnamed): sheet U_MCU_LCDGlass_Symbol/PH0, sheet U_Extension connector/PH0  [a separate net that carries the same name]
(unnamed): sheet U_MCU_LCDGlass_Symbol/SHIELD, sheet U_Touch Sensing/SHIELD  [a separate net that carries the same name]
(unnamed): sheet U_MCU_LCDGlass_Symbol/SAI1_MCKB, sheet U_Audio/SAI1_MCKB  [a separate net that carries the same name]
(unnamed): sheet U_MCU_LCDGlass_Symbol/SAI1_SCKB, sheet U_Audio/SAI1_SCKB  [a separate net that carries the same name]
(unnamed): sheet U_MCU_LCDGlass_Symbol/SAI1_FSB, sheet U_Audio/SAI1_FSB  [a separate net that carries the same name]
(unnamed): sheet U_MCU_LCDGlass_Symbol/SAI1_SDB, sheet U_Audio/SAI1_SDB  [a separate net that carries the same name]
(unnamed): sheet U_MCU_LCDGlass_Symbol/SAI1_SDA, sheet U_Audio/SAI1_SDA  [a separate net that carries the same name]
(unnamed): sheet U_MCU_LCDGlass_Symbol/OpAmp1_INP, sheet U_peripherals/OpAmp1_INP  [a separate net that carries the same name]
(unnamed): sheet U_MCU_LCDGlass_Symbol/Comp2_OUT, sheet U_peripherals/Comp2_OUT  [a separate net that carries the same name]
(unnamed): sheet U_MCU_LCDGlass_Symbol/TKEY, sheet U_Touch Sensing/TKEY  [a separate net that carries the same name]
(unnamed): sheet U_MCU_LCDGlass_Symbol/TKEY_CS, sheet U_Touch Sensing/TKEY_CS  [a separate net that carries the same name]
(unnamed): sheet U_MCU_LCDGlass_Symbol/SHIELD_CS, sheet U_Touch Sensing/SHIELD_CS  [a separate net that carries the same name]
(unnamed): sheet U_MCU_LCDGlass_Symbol/Bootloader_RESET_3V3, sheet U_USART_IrDA/Bootloader_RESET_3V3  [a separate net that carries the same name]
(unnamed): sheet U_MCU_LCDGlass_Symbol/Bootloader_BOOT0_3V3, sheet U_USART_IrDA/Bootloader_BOOT0_3V3  [a separate net that carries the same name]
(unnamed): sheet U_MCU_LCDGlass_Symbol/LPUART_RX_3V3, sheet U_ST_LINK/LPUART_RX_3V3, sheet U_USART_IrDA/LPUART_RX_3V3  [a separate net that carries the same name]
(unnamed): sheet U_MCU_LCDGlass_Symbol/USART1_CTS_3V3, sheet U_USART_IrDA/USART1_CTS_3V3  [a separate net that carries the same name]
(unnamed): sheet U_MCU_LCDGlass_Symbol/USART1/IrDA_RX_3V3, sheet U_USART_IrDA/USART1/IrDA_RX_3V3  [a separate net that carries the same name]
(unnamed): sheet U_MCU_LCDGlass_Symbol/BL_Control, sheet U_LCD_TFT/BL_Control  [a separate net that carries the same name]
(unnamed): sheet U_MCU_LCDGlass_Symbol/EXT_RESET, sheet U_RF_I2C_EEPROM/EXT_RESET  [a separate net that carries the same name]
(unnamed): sheet U_MCU_LCDGlass_Symbol/BOOT0, sheet U_Extension connector/BOOT0  [a separate net that carries the same name]
(unnamed): sheet U_MCU_LCDGlass_Symbol/NFC_NSS, sheet U_SWP_SmartCard_NFC/NFC_NSS  [a separate net that carries the same name]
(unnamed): sheet U_MCU_LCDGlass_Symbol/NFC_MOSI, sheet U_SWP_SmartCard_NFC/NFC_MOSI  [a separate net that carries the same name]
(unnamed): sheet U_MCU_LCDGlass_Symbol/NFC_SCK, sheet U_SWP_SmartCard_NFC/NFC_SCK  [a separate net that carries the same name]
(unnamed): sheet U_MCU_LCDGlass_Symbol/NFC_MISO, sheet U_SWP_SmartCard_NFC/NFC_MISO  [a separate net that carries the same name]
(unnamed): sheet U_MCU_LCDGlass_Symbol/I2C2_SDA, sheet U_RF_I2C_EEPROM/I2C2_SDA  [a separate net that carries the same name]
(unnamed): sheet U_MCU_LCDGlass_Symbol/I2C2_SCL, sheet U_RF_I2C_EEPROM/I2C2_SCL  [a separate net that carries the same name]
(unnamed): sheet U_USART_IrDA/NFC_IRQINN, sheet U_SWP_SmartCard_NFC/NFC_IRQINN  [a separate net that carries the same name]
(unnamed): sheet U_USART_IrDA/NFC_IRQOUTN, sheet U_SWP_SmartCard_NFC/NFC_IRQOUTN  [a separate net that carries the same name]
(unnamed): sheet U_peripherals/VREF+, sheet U_Power/VREF+  [a separate net that carries the same name]

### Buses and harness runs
bus sheet U_Extension connector/PA[0..15] = sheet U_MCU_LCDGlass_Symbol/PA[0..15]
bus sheet U_Extension connector/PB[0..15] = sheet U_MCU_LCDGlass_Symbol/PB[0..15]
bus sheet U_Extension connector/PC[0..15] = sheet U_MCU_LCDGlass_Symbol/PC[0..15]
bus sheet U_Extension connector/PD[0..15] = sheet U_MCU_LCDGlass_Symbol/PD[0..15]
bus sheet U_Extension connector/PE[0..15] = sheet U_MCU_LCDGlass_Symbol/PE[0..15]
bus sheet U_Extension connector/PF[0..15] = sheet U_MCU_LCDGlass_Symbol/PF[0..15]
bus sheet U_Extension connector/PG[0..15] = sheet U_MCU_LCDGlass_Symbol/PG[0..15]
bus sheet U_LCD_TFT/A[0..23] = sheet U_MCU_LCDGlass_Symbol/A[0..23] = sheet U_SRAM&Flash/A[0..23]
bus sheet U_LCD_TFT/D[0..15] = sheet U_MCU_LCDGlass_Symbol/D[0..15] = sheet U_SRAM&Flash/D[0..15]

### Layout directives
rule Matched Net Lengths [Tolerance = 100mil]: (no net found under the mark)
rule Clearance Constraint [Clearance = 10mil]: (no net found under the mark)

## Sheet MCU_LCDGlass_Symbol.SchDoc: MCU_LCDGlassl
size A3; DocumentNumber: 5; Revision: C-02; SheetNumber: 5; SheetTotal: 26; PageSetup: Record=PageOptions¦CenterHorizontal=True¦CenterVertical=True¦PrintScale=1.01¦XCorrection=1.00¦YCorrection=1.00¦PrintKind=1¦BorderSize=5000000¦LeftOffset=0¦BottomOffset=0¦Orientation=2¦PaperLength=1000¦PaperWidth=1000¦Scale=100¦PaperSource=264¦PrintQuality=600¦MediaType=1¦DitherType=10¦PaperKind=A3¦PrintScaleMode=1; Project: STM32L476G-EVAL
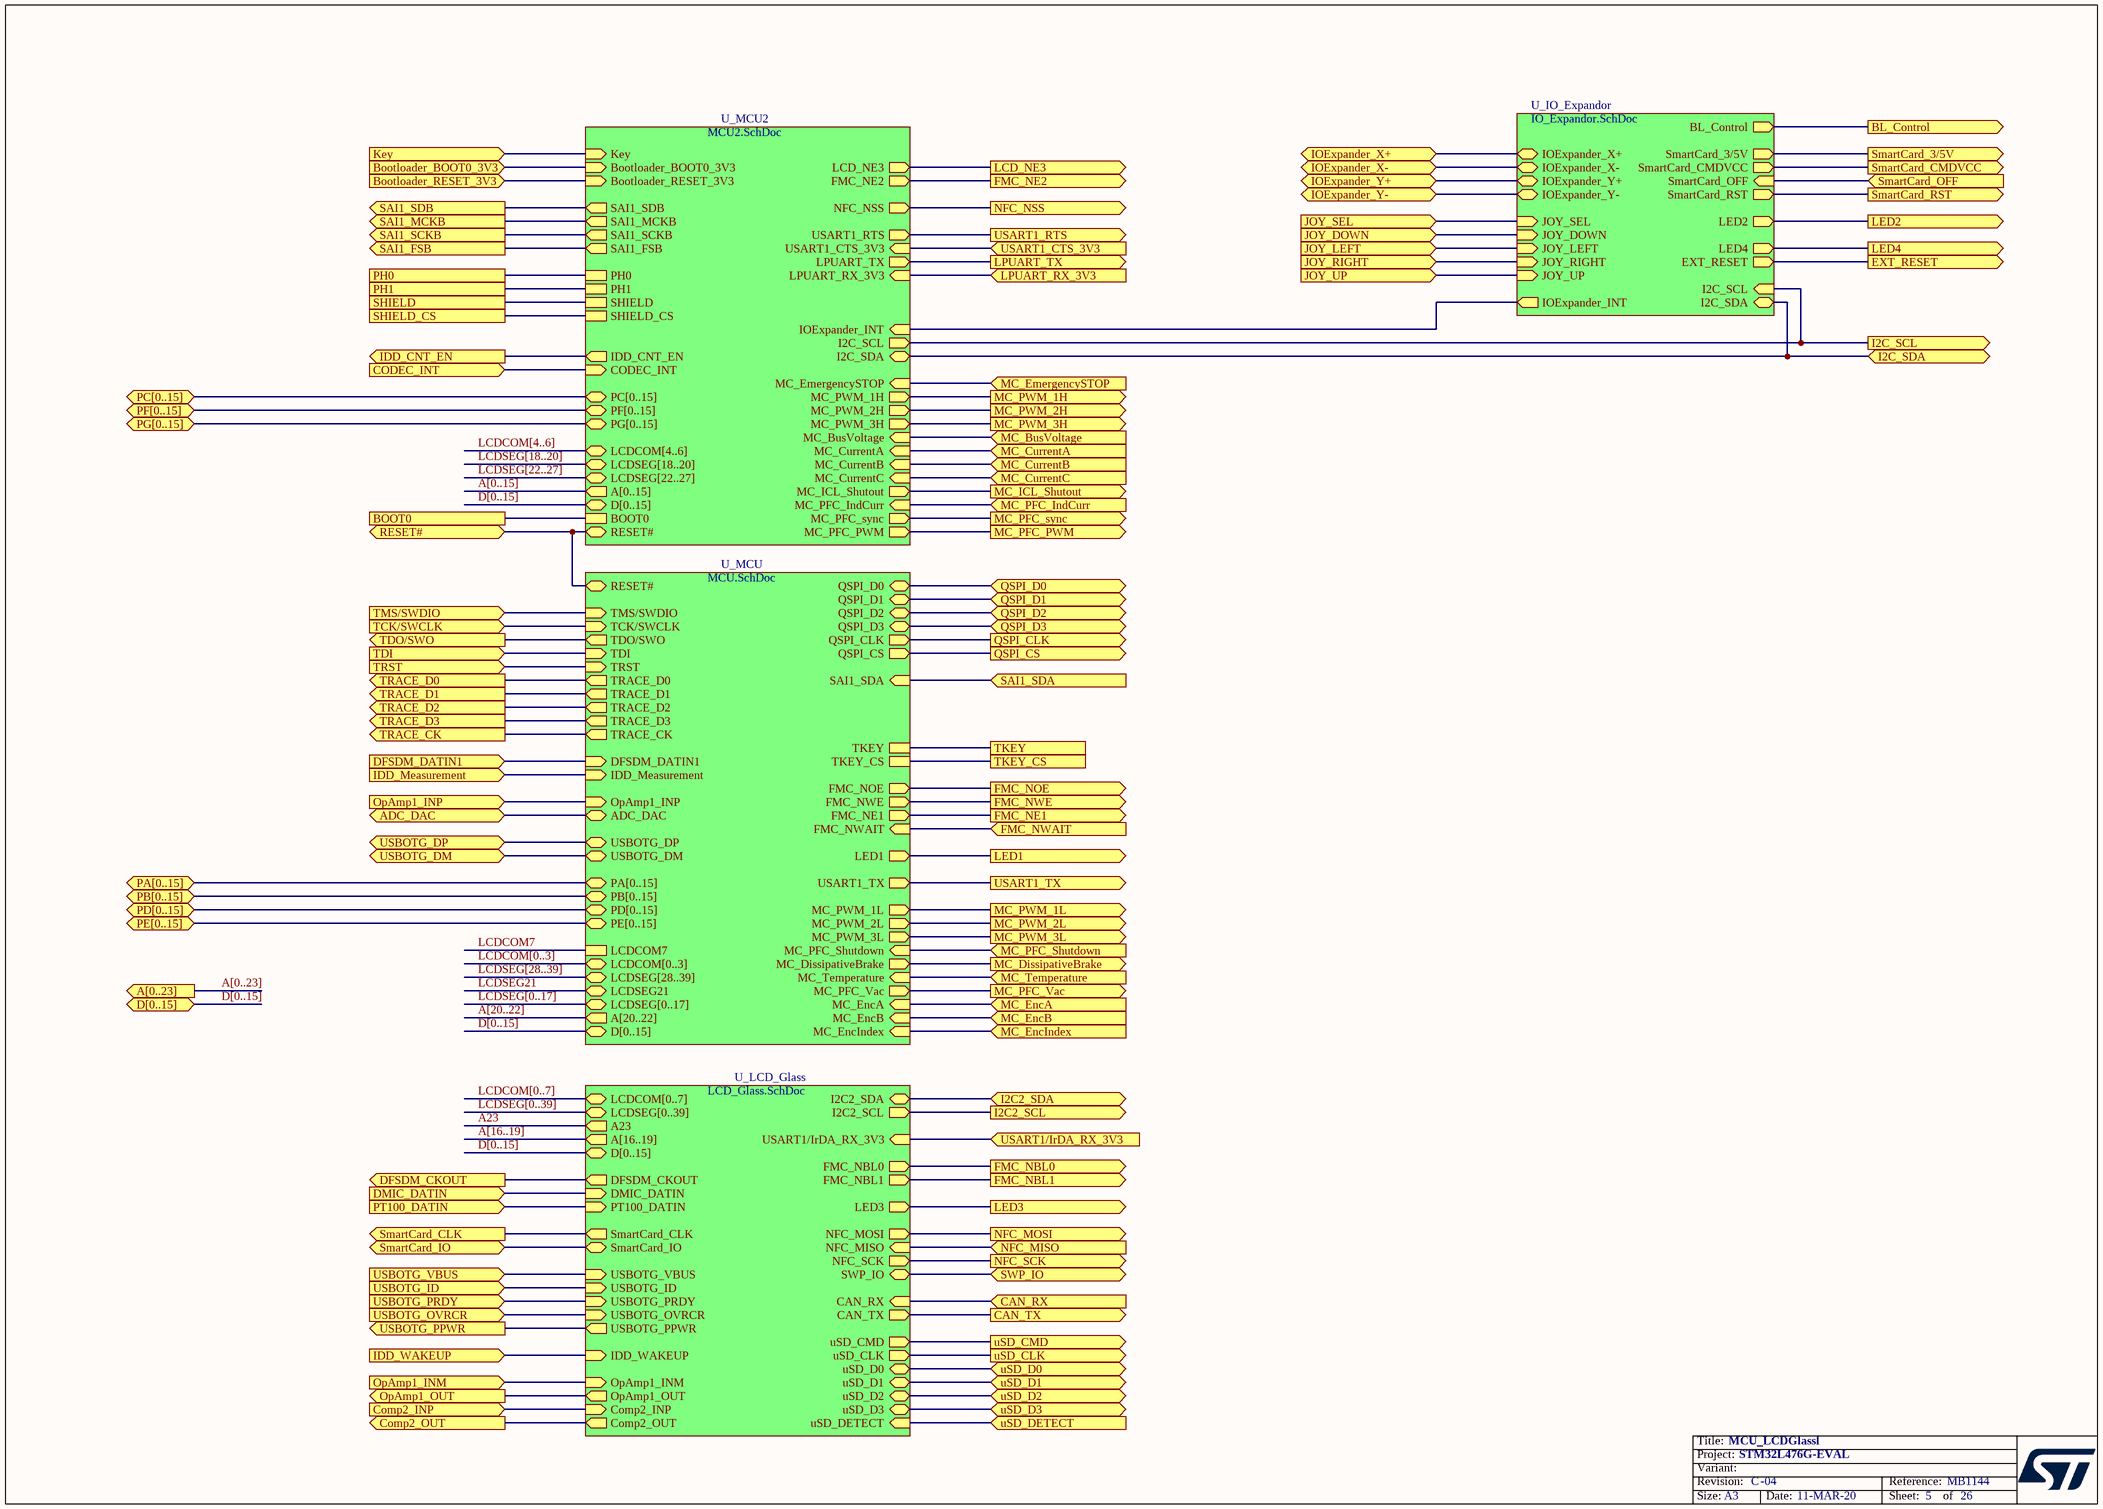
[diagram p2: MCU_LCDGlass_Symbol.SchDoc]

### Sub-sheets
U_IO_Expandor = IO_Expandor.SchDoc: IOExpander_Y+ (bidir), IOExpander_Y- (bidir), IOExpander_X+ (bidir), IOExpander_X- (bidir), IOExpander_INT (out), I2C_SDA (bidir), JOY_SEL (in), JOY_DOWN (in), JOY_LEFT (in), JOY_RIGHT (in), JOY_UP (in), LED4 (out), SmartCard_RST (out), SmartCard_CMDVCC (out), SmartCard_3/5V (out), SmartCard_OFF (in), I2C_SCL (in), LED2 (out), BL_Control (out), EXT_RESET (out)
U_LCD_Glass = LCD_Glass.SchDoc: uSD_CMD (out), uSD_CLK (out), uSD_D3 (bidir), uSD_D2 (bidir), IDD_WAKEUP (in), PT100_DATIN (in), uSD_D0 (bidir), uSD_D1 (bidir), OpAmp1_INM (in), FMC_NBL0 (out), FMC_NBL1 (out), LCDSEG[0..39] (bidir), LCDCOM[0..7] (bidir), USBOTG_VBUS (in), USBOTG_ID (in), CAN_TX (out), SWP_IO (bidir), CAN_RX (in), DMIC_DATIN (in), OpAmp1_OUT (out), Comp2_INP (in), SmartCard_CLK (out), SmartCard_IO (bidir), uSD_DETECT (in), DFSDM_CKOUT (out), D[0..15] (bidir), USBOTG_PRDY (in), USBOTG_OVRCR (in), USBOTG_PPWR (out), Comp2_OUT (out), USART1/IrDA_RX_3V3 (in), A[16..19] (out), A23 (out), NFC_MISO (in), NFC_SCK (out), NFC_MOSI (out), I2C2_SDA (bidir), I2C2_SCL (out), LED3 (out)
U_MCU = MCU.SchDoc: PA[0..15] (bidir), PB[0..15] (bidir), PD[0..15] (bidir), PE[0..15] (bidir), USBOTG_DM (bidir), USBOTG_DP (bidir), TMS/SWDIO (in), TCK/SWCLK (in), DFSDM_DATIN1 (in), FMC_NOE (out), FMC_NWE (out), FMC_NWAIT (in), FMC_NE1 (out), TRACE_D3 (out), TRACE_D1 (out), TRST (in), D[0..15] (bidir), IDD_Measurement (in), USART1_TX (out), LED1 (out), MC_DissipativeBrake (out), TRACE_D2 (out), MC_EncA (in), TDI (in), TDO/SWO (out), ADC_DAC (bidir), RESET# (bidir), QSPI_D3 (bidir), QSPI_D2 (bidir), QSPI_D1 (bidir), QSPI_D0 (bidir), QSPI_CLK (out), QSPI_CS (out), TRACE_D0 (out), TRACE_CK (out), SAI1_SDA (in), OpAmp1_INP (in), MC_PFC_Vac (out), MC_Temperature (in), MC_EncB (in), MC_EncIndex (in), TKEY, TKEY_CS, MC_PWM_1L (out), MC_PWM_2L (out), MC_PWM_3L (out), MC_PFC_Shutdown (in), A[20..22] (out), LCDCOM[0..3] (bidir), LCDCOM7, LCDSEG[0..17] (bidir), LCDSEG[28..39] (bidir), LCDSEG21 (bidir)
U_MCU2 = MCU2.SchDoc: PC[0..15] (bidir), Bootloader_BOOT0_3V3 (in), Bootloader_RESET_3V3 (in), Key (in), CODEC_INT (in), USART1_CTS_3V3 (in), FMC_NE2 (out), USART1_RTS (out), PF[0..15] (bidir), PG[0..15] (bidir), D[0..15] (bidir), MC_PFC_sync (out), IDD_CNT_EN (out), LPUART_TX (out), LPUART_RX_3V3 (in), LCD_NE3 (out), IOExpander_INT (in), I2C_SCL (out), I2C_SDA (bidir), RESET# (bidir), PH1, PH0, SHIELD, SAI1_SDB (out), SAI1_MCKB (out), SAI1_SCKB (out), SAI1_FSB (out), MC_ICL_Shutout (out), MC_PFC_PWM (out), MC_CurrentB (in), MC_CurrentC (in), MC_CurrentA (in), MC_PFC_IndCurr (in), MC_BusVoltage (in), MC_PWM_1H (out), SHIELD_CS, MC_PWM_2H (out), MC_PWM_3H (out), MC_EmergencySTOP (in), A[0..15] (out), LCDSEG[18..20] (bidir), LCDCOM[4..6] (bidir), LCDSEG[22..27] (bidir), BOOT0, NFC_NSS (out)

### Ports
A[0..23] (out), ADC_DAC (bidir), BL_Control (out), BOOT0, Bootloader_BOOT0_3V3 (in), Bootloader_RESET_3V3 (in), CAN_RX (in), CAN_TX (out), CODEC_INT (in), Comp2_INP (in), Comp2_OUT (out), D[0..15] (bidir), DFSDM_CKOUT (out), DFSDM_DATIN1 (in), DMIC_DATIN (in), EXT_RESET (out), FMC_NBL0 (out), FMC_NBL1 (out), FMC_NE1 (out), FMC_NE2 (out), FMC_NOE (out), FMC_NWAIT (in), FMC_NWE (out), I2C2_SCL (out), I2C2_SDA (bidir), I2C_SCL (out), I2C_SDA (bidir), IDD_CNT_EN (out), IDD_Measurement (in), IDD_WAKEUP (in), IOExpander_X+ (bidir), IOExpander_X- (bidir), IOExpander_Y+ (bidir), IOExpander_Y- (bidir), JOY_DOWN (in), JOY_LEFT (in), JOY_RIGHT (in), JOY_SEL (in), JOY_UP (in), Key (in), LCD_NE3 (out), LED1 (out), LED2 (out), LED3 (out), LED4 (out), LPUART_RX_3V3 (in), LPUART_TX (out), MC_BusVoltage (in), MC_CurrentA (in), MC_CurrentB (in), MC_CurrentC (in), MC_DissipativeBrake (out), MC_EmergencySTOP (in), MC_EncA (in), MC_EncB (in), MC_EncIndex (in), MC_ICL_Shutout (out), MC_PFC_IndCurr (in), MC_PFC_PWM (out), MC_PFC_Shutdown (in), MC_PFC_sync (out), MC_PFC_Vac (out), MC_PWM_1H (out), MC_PWM_1L (out), MC_PWM_2H (out), MC_PWM_2L (out), MC_PWM_3H (out), MC_PWM_3L (out), MC_Temperature (in), NFC_MISO (in), NFC_MOSI (out), NFC_NSS (out), NFC_SCK (out), OpAmp1_INM (in), OpAmp1_INP (in), OpAmp1_OUT (out), PA[0..15] (bidir), PB[0..15] (bidir), PC[0..15] (bidir), PD[0..15] (bidir), PE[0..15] (bidir), PF[0..15] (bidir), PG[0..15] (bidir), PH0, PH1, PT100_DATIN (in), QSPI_CLK (out), QSPI_CS (out), QSPI_D0 (bidir), QSPI_D1 (bidir), QSPI_D2 (bidir), QSPI_D3 (bidir), RESET# (bidir), SAI1_FSB (out), SAI1_MCKB (out), SAI1_SCKB (out), SAI1_SDA (in), SAI1_SDB (out), SHIELD, SHIELD_CS, SmartCard_3/5V (out), SmartCard_CLK (out), SmartCard_CMDVCC (out), SmartCard_IO (bidir), SmartCard_OFF (in), SmartCard_RST (out), SWP_IO (bidir), TCK/SWCLK (in), TDI (in), TDO/SWO (out), TKEY, TKEY_CS, TMS/SWDIO (in), TRACE_CK (out), TRACE_D0 (out), TRACE_D1 (out), TRACE_D2 (out), TRACE_D3 (out), TRST (in), USART1/IrDA_RX_3V3 (in), USART1_CTS_3V3 (in), USART1_RTS (out), USART1_TX (out), USBOTG_DM (bidir), USBOTG_DP (bidir), USBOTG_ID (in), USBOTG_OVRCR (in), USBOTG_PPWR (out), USBOTG_PRDY (in), USBOTG_VBUS (in), uSD_CLK (out), uSD_CMD (out), uSD_D0 (bidir), uSD_D1 (bidir), uSD_D2 (bidir), uSD_D3 (bidir), uSD_DETECT (in)

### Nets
BOOT0: port BOOT0, sheet U_MCU2/BOOT0
Comp2_INP: port Comp2_INP, sheet U_LCD_Glass/Comp2_INP
Comp2_OUT: port Comp2_OUT, sheet U_LCD_Glass/Comp2_OUT
I2C_SCL: port I2C_SCL, sheet U_IO_Expandor/I2C_SCL, sheet U_MCU2/I2C_SCL
I2C_SDA: port I2C_SDA, sheet U_IO_Expandor/I2C_SDA, sheet U_MCU2/I2C_SDA
LCD_NE3: port LCD_NE3, sheet U_MCU2/LCD_NE3
LCDSEG7: port TDO/SWO, sheet U_MCU/TDO/SWO
LCDSEG8: port TRST, sheet U_MCU/TRST
LCDSEG17: port TDI, sheet U_MCU/TDI
OpAmp1_INM: port OpAmp1_INM, sheet U_LCD_Glass/OpAmp1_INM
OpAmp1_INP: port OpAmp1_INP, sheet U_MCU/OpAmp1_INP
OpAmp1_OUT: port OpAmp1_OUT, sheet U_LCD_Glass/OpAmp1_OUT
PA4: port ADC_DAC, sheet U_MCU/ADC_DAC
PA11: port USBOTG_DM, sheet U_MCU/USBOTG_DM
PA12: port USBOTG_DP, sheet U_MCU/USBOTG_DP
PA13: port TMS/SWDIO, sheet U_MCU/TMS/SWDIO
PA14: port TCK/SWCLK, sheet U_MCU/TCK/SWCLK
PB6: port USART1_TX, sheet U_MCU/USART1_TX
PC13: port Key, sheet U_MCU2/Key
PD3: port DFSDM_DATIN1, sheet U_MCU/DFSDM_DATIN1
PD4: port FMC_NOE, sheet U_MCU/FMC_NOE
PD5: port FMC_NWE, sheet U_MCU/FMC_NWE
PD7: port FMC_NE1, sheet U_MCU/FMC_NE1
PF11: port NFC_NSS, sheet U_MCU2/NFC_NSS
PG8: port LPUART_RX_3V3, sheet U_MCU2/LPUART_RX_3V3
PG9: port FMC_NE2, sheet U_MCU2/FMC_NE2
PG11: port USART1_CTS_3V3, sheet U_MCU2/USART1_CTS_3V3
PG12: port USART1_RTS, sheet U_MCU2/USART1_RTS
PH0: port PH0, sheet U_MCU2/PH0
PH1: port PH1, sheet U_MCU2/PH1
RESET#: port RESET#, sheet U_MCU/RESET#, sheet U_MCU2/RESET#
NetB3_1: port JOY_LEFT, sheet U_IO_Expandor/JOY_LEFT
NetB3_2: port JOY_SEL, sheet U_IO_Expandor/JOY_SEL
NetB3_3: port JOY_DOWN, sheet U_IO_Expandor/JOY_DOWN
NetB3_4: port JOY_RIGHT, sheet U_IO_Expandor/JOY_RIGHT
NetB3_6: port JOY_UP, sheet U_IO_Expandor/JOY_UP
NetC1_2: port MC_EncB, sheet U_MCU/MC_EncB
NetC2_2: port MC_EncIndex, sheet U_MCU/MC_EncIndex
NetC3_1: port MC_PFC_IndCurr, sheet U_MCU2/MC_PFC_IndCurr
NetC4_2: port MC_EncA, sheet U_MCU/MC_EncA
NetC5_2: port MC_PFC_Shutdown, sheet U_MCU/MC_PFC_Shutdown
NetC6_2: port MC_PFC_Vac, sheet U_MCU/MC_PFC_Vac
NetC7_2: port MC_EmergencySTOP, sheet U_MCU2/MC_EmergencySTOP
NetC9_2: port MC_PFC_PWM, sheet U_MCU2/MC_PFC_PWM
NetC10_2: port MC_CurrentC, sheet U_MCU2/MC_CurrentC
NetC11_1: port MC_BusVoltage, sheet U_MCU2/MC_BusVoltage
NetC13_2: port MC_CurrentB, sheet U_MCU2/MC_CurrentB
NetC14_2: port MC_CurrentA, sheet U_MCU2/MC_CurrentA
NetC15_1: port USBOTG_VBUS, port USBOTG_PRDY, sheet U_LCD_Glass/USBOTG_VBUS, sheet U_LCD_Glass/USBOTG_PRDY
NetC16_2: port MC_PFC_sync, sheet U_MCU2/MC_PFC_sync
NetC17_1: port MC_Temperature, sheet U_MCU/MC_Temperature
NetC34_2: port SHIELD_CS, sheet U_MCU2/SHIELD_CS
NetC37_2: port TKEY_CS, sheet U_MCU/TKEY_CS
NetC73_1: port IDD_Measurement, sheet U_MCU/IDD_Measurement
NetCN2_3: port MC_PWM_1H, sheet U_MCU2/MC_PWM_1H
NetCN2_5: port MC_PWM_1L, sheet U_MCU/MC_PWM_1L
NetCN2_7: port MC_PWM_2H, sheet U_MCU2/MC_PWM_2H
NetCN2_9: port MC_PWM_2L, sheet U_MCU/MC_PWM_2L
NetCN2_11: port MC_PWM_3H, sheet U_MCU2/MC_PWM_3H
NetCN2_13: port MC_PWM_3L, sheet U_MCU/MC_PWM_3L
NetCN2_21: port MC_ICL_Shutout, sheet U_MCU2/MC_ICL_Shutout
NetCN2_23: port MC_DissipativeBrake, sheet U_MCU/MC_DissipativeBrake
NetCN3_4: port EXT_RESET, sheet U_IO_Expandor/EXT_RESET
NetCN11_4: port uSD_DETECT, sheet U_LCD_Glass/uSD_DETECT
NetCN11_6: port USBOTG_ID, sheet U_LCD_Glass/USBOTG_ID
NetCN11_8: port CAN_TX, sheet U_LCD_Glass/CAN_TX
NetCN11_16: port NFC_MISO, sheet U_LCD_Glass/NFC_MISO
NetCN11_18: port NFC_SCK, sheet U_LCD_Glass/NFC_SCK
NetCN11_20: port SWP_IO, sheet U_LCD_Glass/SWP_IO
NetCN11_24: port CAN_RX, sheet U_LCD_Glass/CAN_RX
NetCN11_26: port NFC_MOSI, sheet U_LCD_Glass/NFC_MOSI
NetCN11_28: port DFSDM_CKOUT, sheet U_LCD_Glass/DFSDM_CKOUT
NetCN11_30: port LED3, sheet U_LCD_Glass/LED3
NetCN11_32: port DMIC_DATIN, sheet U_LCD_Glass/DMIC_DATIN
NetCN12_12: port TRACE_CK, sheet U_MCU/TRACE_CK
NetCN12_18: port TRACE_D2, sheet U_MCU/TRACE_D2
NetCN12_20: port TRACE_D3, sheet U_MCU/TRACE_D3
NetCN14_2: port uSD_CMD, sheet U_LCD_Glass/uSD_CMD
NetCN14_10: port USART1/IrDA_RX_3V3, sheet U_LCD_Glass/USART1/IrDA_RX_3V3
NetCN14_40: port FMC_NBL0, sheet U_LCD_Glass/FMC_NBL0
NetCN14_42: port FMC_NBL1, sheet U_LCD_Glass/FMC_NBL1
NetCN18_1: port uSD_D2, sheet U_LCD_Glass/uSD_D2
NetCN18_2: port uSD_D3, sheet U_LCD_Glass/uSD_D3
NetCN18_5: port uSD_CLK, sheet U_LCD_Glass/uSD_CLK
NetCN18_7: port uSD_D0, sheet U_LCD_Glass/uSD_D0
NetCN18_8: port uSD_D1, sheet U_LCD_Glass/uSD_D1
NetCN19_31: port IOExpander_X-, sheet U_IO_Expandor/IOExpander_X-
NetCN19_32: port IOExpander_X+, sheet U_IO_Expandor/IOExpander_X+
NetCN19_33: port IOExpander_Y-, sheet U_IO_Expandor/IOExpander_Y-
NetCN19_34: port IOExpander_Y+, sheet U_IO_Expandor/IOExpander_Y+
NetD4_2: port Bootloader_RESET_3V3, sheet U_MCU2/Bootloader_RESET_3V3
NetJP19_1: port USBOTG_PPWR, sheet U_LCD_Glass/USBOTG_PPWR
NetLD6_2: port USBOTG_OVRCR, sheet U_LCD_Glass/USBOTG_OVRCR
NetR24_1: port PT100_DATIN, sheet U_LCD_Glass/PT100_DATIN
NetR32_2: port FMC_NWAIT, sheet U_MCU/FMC_NWAIT
NetR34_1: port LPUART_TX, sheet U_MCU2/LPUART_TX
NetR35_1: port CODEC_INT, sheet U_MCU2/CODEC_INT
NetR37_1: port SHIELD, sheet U_MCU2/SHIELD
NetR39_1: port TKEY, sheet U_MCU/TKEY
NetR53_2: port SAI1_SDA, sheet U_MCU/SAI1_SDA
NetR54_2: port LED1, sheet U_MCU/LED1
NetR59_2: port Bootloader_BOOT0_3V3, sheet U_MCU2/Bootloader_BOOT0_3V3
NetR71_2: port QSPI_CS, sheet U_MCU/QSPI_CS
NetR89_1: port SAI1_SCKB, sheet U_MCU2/SAI1_SCKB
NetR90_1: port SAI1_FSB, sheet U_MCU2/SAI1_FSB
NetR91_1: port IDD_CNT_EN, sheet U_MCU2/IDD_CNT_EN
NetR104_1: port TRACE_D0, sheet U_MCU/TRACE_D0
NetR105_1: port SAI1_SDB, sheet U_MCU2/SAI1_SDB
NetR106_1: port SAI1_MCKB, sheet U_MCU2/SAI1_MCKB
NetR107_1: port SmartCard_CLK, sheet U_LCD_Glass/SmartCard_CLK
NetR137_1: port IDD_WAKEUP, sheet U_LCD_Glass/IDD_WAKEUP
NetR143_1: port SmartCard_IO, sheet U_LCD_Glass/SmartCard_IO
NetR156_2: port TRACE_D1, sheet U_MCU/TRACE_D1
NetR213_1: port SmartCard_OFF, sheet U_IO_Expandor/SmartCard_OFF
NetR214_2: port SmartCard_RST, sheet U_IO_Expandor/SmartCard_RST
NetR215_2: port SmartCard_CMDVCC, sheet U_IO_Expandor/SmartCard_CMDVCC
NetR241_1: port SmartCard_3/5V, sheet U_IO_Expandor/SmartCard_3/5V
NetR255_1: port LED4, sheet U_IO_Expandor/LED4
NetR257_1: port LED2, sheet U_IO_Expandor/LED2
NetR260_1: port BL_Control, sheet U_IO_Expandor/BL_Control
NetR263_2: port I2C2_SDA, sheet U_LCD_Glass/I2C2_SDA
NetR264_2: port I2C2_SCL, sheet U_LCD_Glass/I2C2_SCL
NetSB9_1: port QSPI_CLK, sheet U_MCU/QSPI_CLK
NetSB12_1: port QSPI_D0, sheet U_MCU/QSPI_D0
NetSB14_1: port QSPI_D1, sheet U_MCU/QSPI_D1
NetSB18_1: port QSPI_D2, sheet U_MCU/QSPI_D2
NetSB21_1: port QSPI_D3, sheet U_MCU/QSPI_D3
(unnamed): sheet U_IO_Expandor/IOExpander_INT, sheet U_MCU2/IOExpander_INT

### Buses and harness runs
bus A[0..15] = sheet U_MCU2/A[0..15]
bus A[0..23] = port A[0..23]
bus A[16..19] = sheet U_LCD_Glass/A[16..19]
bus A[20..22] = sheet U_MCU/A[20..22]
bus D[0..15] = port D[0..15]
bus D[0..15] = sheet U_LCD_Glass/D[0..15]
bus D[0..15] = sheet U_MCU2/D[0..15]
bus D[0..15] = sheet U_MCU/D[0..15]
bus LCDCOM[0..3] = sheet U_MCU/LCDCOM[0..3]
bus LCDCOM[0..7] = sheet U_LCD_Glass/LCDCOM[0..7]
bus LCDCOM[4..6] = sheet U_MCU2/LCDCOM[4..6]
bus LCDSEG[0..17] = sheet U_MCU/LCDSEG[0..17]
bus LCDSEG[0..39] = sheet U_LCD_Glass/LCDSEG[0..39]
bus LCDSEG[18..20] = sheet U_MCU2/LCDSEG[18..20]
bus LCDSEG[22..27] = sheet U_MCU2/LCDSEG[22..27]
bus LCDSEG[28..39] = sheet U_MCU/LCDSEG[28..39]
bus port PA[0..15] = sheet U_MCU/PA[0..15]
bus port PB[0..15] = sheet U_MCU/PB[0..15]
bus port PC[0..15] = sheet U_MCU2/PC[0..15]
bus port PD[0..15] = sheet U_MCU/PD[0..15]
bus port PE[0..15] = sheet U_MCU/PE[0..15]
bus port PF[0..15] = sheet U_MCU2/PF[0..15]
bus port PG[0..15] = sheet U_MCU2/PG[0..15]

## Sheet MCU.SchDoc: MCU
size A3; DocumentNumber: 3; Revision: C-02; SheetNumber: 3; SheetTotal: 26; PageSetup: Record=PageOptions¦CenterHorizontal=True¦CenterVertical=True¦PrintScale=1.04¦XCorrection=1.00¦YCorrection=1.00¦PrintKind=1¦BorderSize=5000000¦LeftOffset=0¦BottomOffset=0¦Orientation=2¦PaperLength=1000¦PaperWidth=1000¦Scale=100¦PaperSource=7¦PrintQuality=600¦MediaType=1¦DitherType=10¦PaperKind=A3¦PrintScaleMode=1; Project: STM32L476G-EVAL
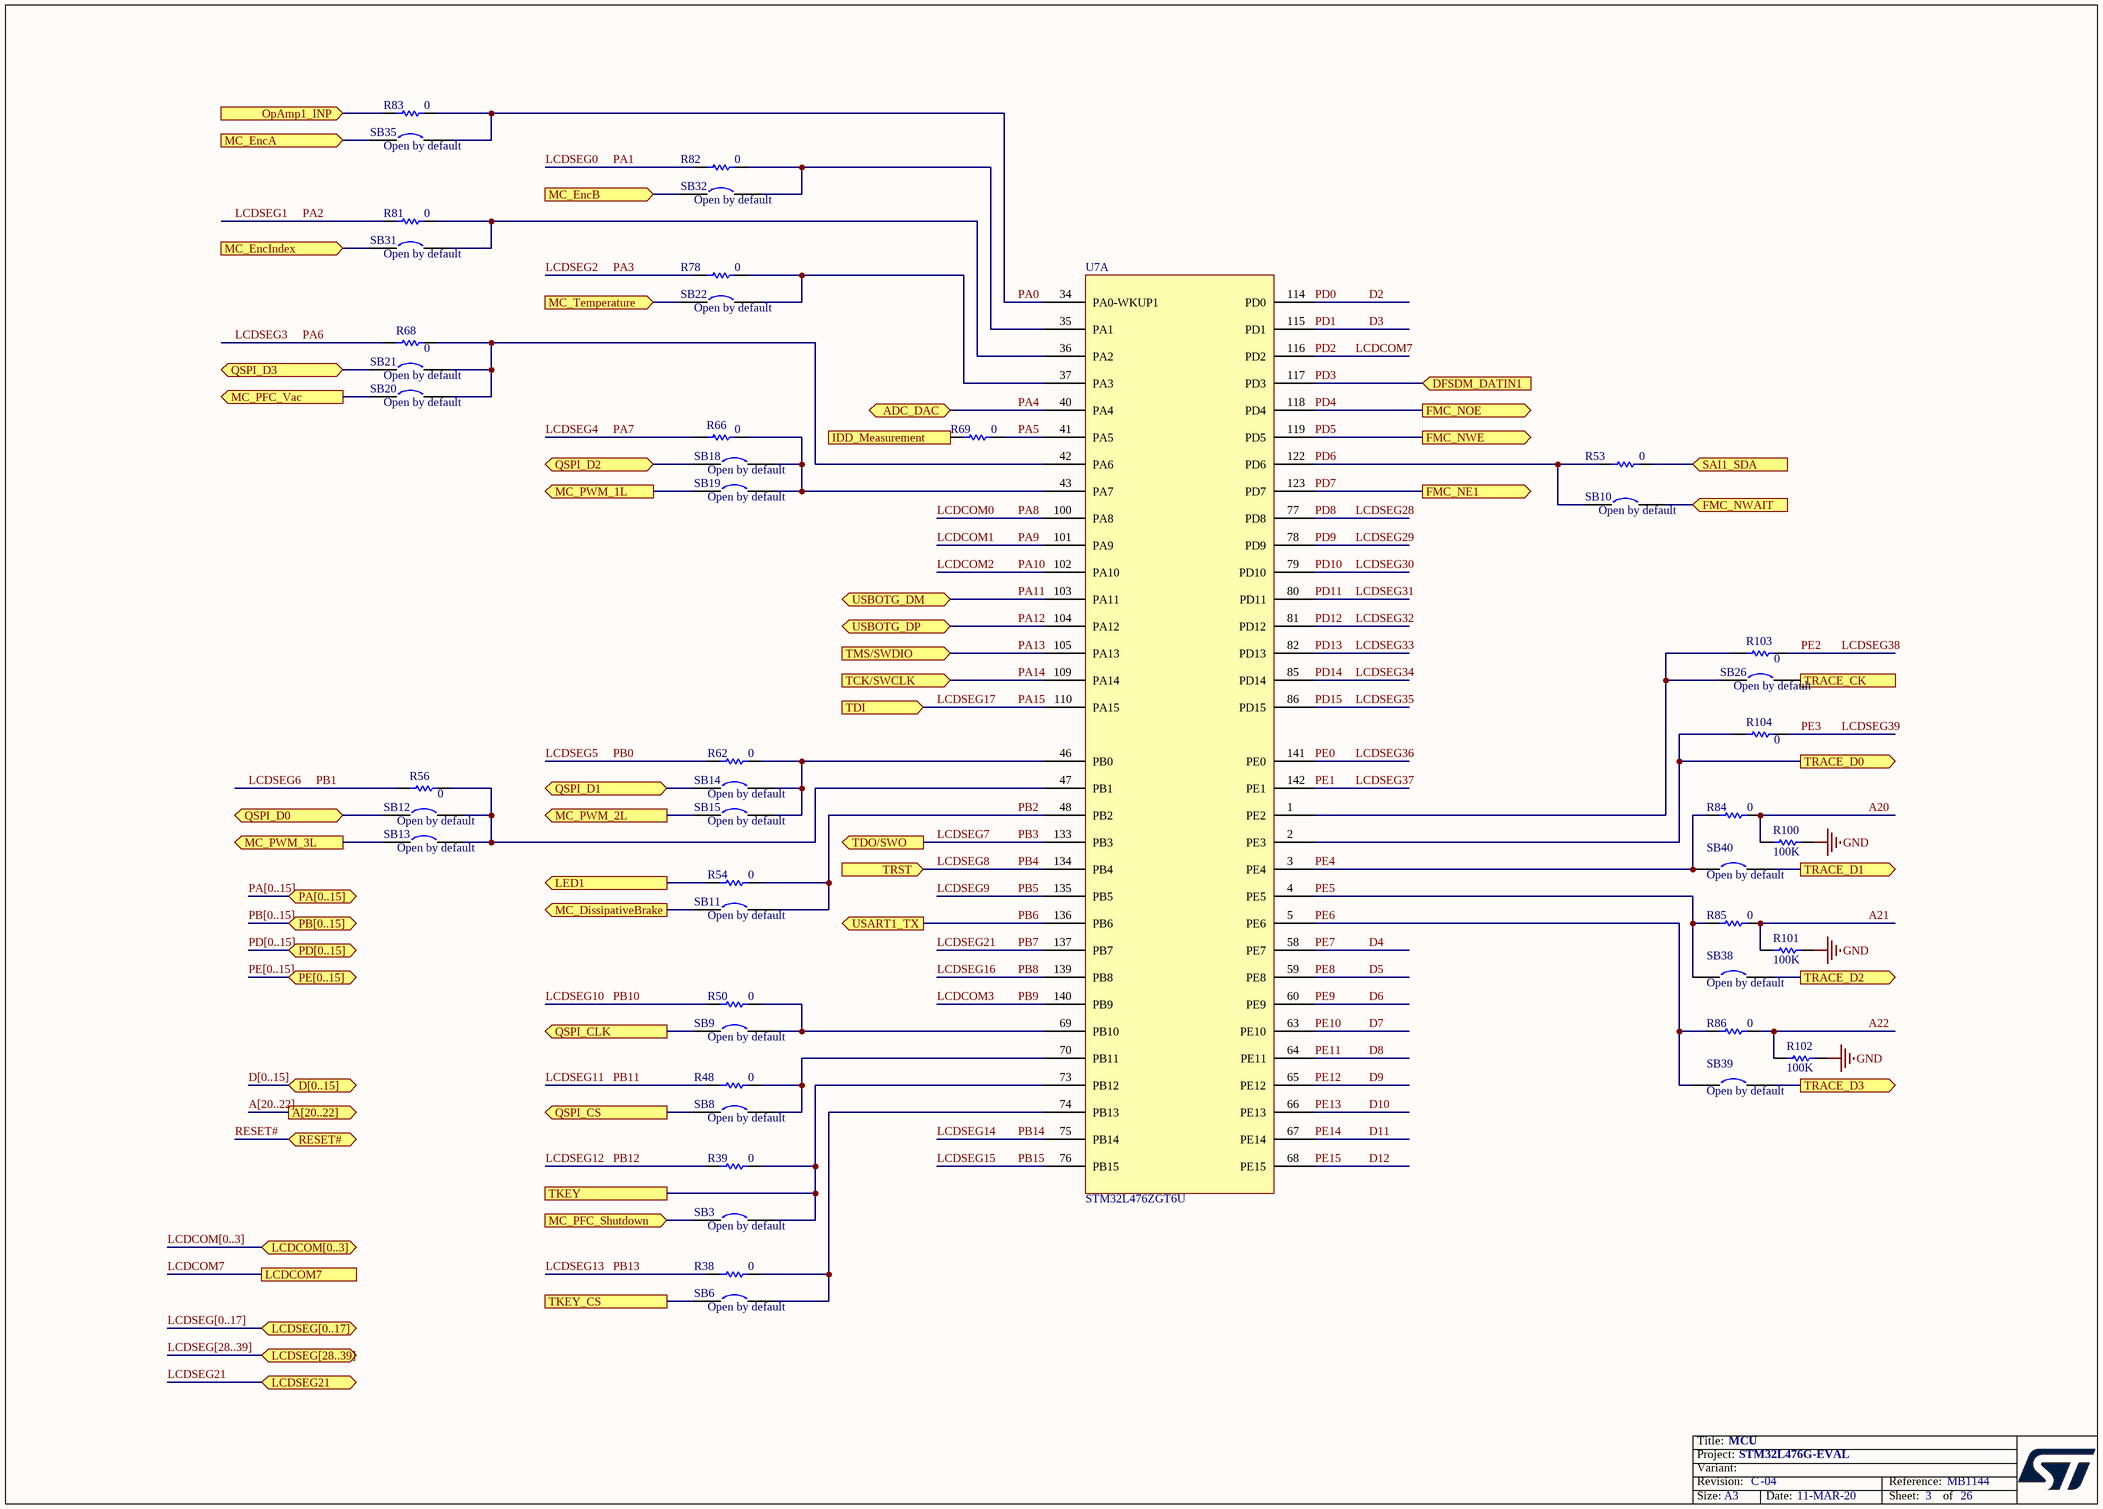
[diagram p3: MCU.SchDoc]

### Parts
R38  0  [SB_0603]
R39  0  [SB_0603]
R48  0  [SB_0603]
R50  0  [SB_0603]
R53  0  [SB_0603]
R54  0  [SB_0603]
R56  0  [SB_0603]
R62  0  [SB_0603]
R66  0  [SB_0603]
R68  0  [SB_0603]
R69  0  [0603R]
R78  0  [SB_0603]
R81  0  [SB_0603]
R82  0  [SB_0603]
R83  0  [SB_0603]
R84  0  [SB_0603]
R85  0  [SB_0603]
R86  0  [SB_0603]
R100  100K  [0402R]
R101  100K  [0402R]
R102  100K  [0402R]
R103  0  [SB_0603]
R104  0  [SB_0603]
SB3  Open by default  [SB_0603]
SB6  Open by default  [SB_0603]
SB8  Open by default  [SB_0603]
SB9  Open by default  [SB_0603]
SB10  Open by default  [SB_0603]
SB11  Open by default  [SB_0603]
SB12  Open by default  [SB_0603]
SB13  Open by default  [SB_0603]
SB14  Open by default  [SB_0603]
SB15  Open by default  [SB_0603]
SB18  Open by default  [SB_0603]
SB19  Open by default  [SB_0603]
SB20  Open by default  [SB_0603]
SB21  Open by default  [SB_0603]
SB22  Open by default  [SB_0603]
SB26  Open by default  [SB_0603]
SB31  Open by default  [SB_0603]
SB32  Open by default  [SB_0603]
SB35  Open by default  [SB_0603]
SB38  Open by default  [SB_0603]
SB39  Open by default  [SB_0603]
SB40  Open by default  [SB_0603]
U7  STM32L476ZGT6U  [TQFP144_0R5_22X22_SOCKET]  (part A of 3)

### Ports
A[20..22] (out), ADC_DAC (bidir), D[0..15] (bidir), DFSDM_DATIN1 (in), FMC_NE1 (out), FMC_NOE (out), FMC_NWAIT (in), FMC_NWE (out), IDD_Measurement (in), LCDCOM7, LCDCOM[0..3] (bidir), LCDSEG21 (bidir), LCDSEG[0..17] (bidir), LCDSEG[28..39] (bidir), LED1 (out), MC_DissipativeBrake (out), MC_EncA (in), MC_EncB (in), MC_EncIndex (in), MC_PFC_Shutdown (in), MC_PFC_Vac (out), MC_PWM_1L (out), MC_PWM_2L (out), MC_PWM_3L (out), MC_Temperature (in), OpAmp1_INP (in), PA[0..15] (bidir), PB[0..15] (bidir), PD[0..15] (bidir), PE[0..15] (bidir), QSPI_CLK (out), QSPI_CS (out), QSPI_D0 (bidir), QSPI_D1 (bidir), QSPI_D2 (bidir), QSPI_D3 (bidir), RESET# (bidir), SAI1_SDA (in), TCK/SWCLK (in), TDI (in), TDO/SWO (out), TKEY, TKEY_CS, TMS/SWDIO (in), TRACE_CK (out), TRACE_D0 (out), TRACE_D1 (out), TRACE_D2 (out), TRACE_D3 (out), TRST (in), USART1_TX (out), USBOTG_DM (bidir), USBOTG_DP (bidir)

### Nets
GND: R100.2 R101.2 R102.2
A20: R84.1 R100.1
A21: R85.1 R101.1
A22: R86.1 R102.1
D2: U7.114(PD0)  [also labelled PD0]
D3: U7.115(PD1)  [also labelled PD1]
D4: U7.58(PE7)  [also labelled PE7]
D5: U7.59(PE8)  [also labelled PE8]
D6: U7.60(PE9)  [also labelled PE9]
D7: U7.63(PE10)  [also labelled PE10]
D8: U7.64(PE11)  [also labelled PE11]
D9: U7.65(PE12)  [also labelled PE12]
D10: U7.66(PE13)  [also labelled PE13]
D11: U7.67(PE14)  [also labelled PE14]
D12: U7.68(PE15)  [also labelled PE15]
LCDCOM0: U7.100(PA8)  [also labelled PA8]
LCDCOM1: U7.101(PA9)  [also labelled PA9]
LCDCOM2: U7.102(PA10)  [also labelled PA10]
LCDCOM3: U7.140(PB9)  [also labelled PB9]
LCDCOM7: U7.116(PD2) ; port LCDCOM7  [also labelled PD2]
LCDSEG0: R82.1  [also labelled PA1]
LCDSEG1: R81.1  [also labelled PA2]
LCDSEG2: R78.2  [also labelled PA3]
LCDSEG3: R68.1  [also labelled PA6]
LCDSEG4: R66.1  [also labelled PA7]
LCDSEG5: R62.1  [also labelled PB0]
LCDSEG6: R56.1  [also labelled PB1]
LCDSEG7: U7.133(PB3) ; port TDO/SWO  [also labelled PB3]
LCDSEG8: U7.134(PB4) ; port TRST  [also labelled PB4]
LCDSEG9: U7.135(PB5)  [also labelled PB5]
LCDSEG10: R50.1  [also labelled PB10]
LCDSEG11: R48.1  [also labelled PB11]
LCDSEG12: R39.2  [also labelled PB12]
LCDSEG13: R38.1  [also labelled PB13]
LCDSEG14: U7.75(PB14)  [also labelled PB14]
LCDSEG15: U7.76(PB15)  [also labelled PB15]
LCDSEG16: U7.139(PB8)  [also labelled PB8]
LCDSEG17: U7.110(PA15) ; port TDI  [also labelled PA15]
LCDSEG21: U7.137(PB7) ; port LCDSEG21  [also labelled PB7]
LCDSEG28: U7.77(PD8)  [also labelled PD8]
LCDSEG29: U7.78(PD9)  [also labelled PD9]
LCDSEG30: U7.79(PD10)  [also labelled PD10]
LCDSEG31: U7.80(PD11)  [also labelled PD11]
LCDSEG32: U7.81(PD12)  [also labelled PD12]
LCDSEG33: U7.82(PD13)  [also labelled PD13]
LCDSEG34: U7.85(PD14)  [also labelled PD14]
LCDSEG35: U7.86(PD15)  [also labelled PD15]
LCDSEG36: U7.141(PE0)  [also labelled PE0]
LCDSEG37: U7.142(PE1)  [also labelled PE1]
LCDSEG38: R103.2  [also labelled PE2]
LCDSEG39: R104.2  [also labelled PE3]
OpAmp1_INP: R83.2 ; port OpAmp1_INP
PA0: R83.1 SB35.2 U7.34(PA0-WKUP1)
PA4: U7.40(PA4) ; port ADC_DAC
PA5: R69.1 U7.41(PA5)
PA11: U7.103(PA11) ; port USBOTG_DM
PA12: U7.104(PA12) ; port USBOTG_DP
PA13: U7.105(PA13) ; port TMS/SWDIO
PA14: U7.109(PA14) ; port TCK/SWCLK
PB2: R54.1 SB11.2 U7.48(PB2)
PB6: U7.136(PB6) ; port USART1_TX
PD3: U7.117(PD3) ; port DFSDM_DATIN1
PD4: U7.118(PD4) ; port FMC_NOE
PD5: U7.119(PD5) ; port FMC_NWE
PD6: R53.1 SB10.1 U7.122(PD6)
PD7: U7.123(PD7) ; port FMC_NE1
PE4: R84.2 SB40.1 U7.3(PE4)
PE5: R85.2 SB38.1 U7.4(PE5)
PE6: R86.2 SB39.1 U7.5(PE6)
NetC1_2: SB32.1 ; port MC_EncB
NetC2_2: SB31.1 ; port MC_EncIndex
NetC4_2: SB35.1 ; port MC_EncA
NetC5_2: SB3.1 ; port MC_PFC_Shutdown
NetC6_2: SB20.1 ; port MC_PFC_Vac
NetC17_1: SB22.1 ; port MC_Temperature
NetC37_2: SB6.1 ; port TKEY_CS
NetC73_1: R69.2 ; port IDD_Measurement
NetCN2_5: SB19.1 ; port MC_PWM_1L
NetCN2_9: SB15.1 ; port MC_PWM_2L
NetCN2_13: SB13.1 ; port MC_PWM_3L
NetCN2_23: SB11.1 ; port MC_DissipativeBrake
NetCN12_12: SB26.2 ; port TRACE_CK
NetCN12_18: SB38.2 ; port TRACE_D2
NetCN12_20: SB39.2 ; port TRACE_D3
NetR32_2: SB10.2 ; port FMC_NWAIT
NetR38_2: R38.2 SB6.2 U7.74(PB13)
NetR39_1: R39.1 SB3.2 U7.73(PB12) ; port TKEY
NetR48_2: R48.2 SB8.2 U7.70(PB11)
NetR50_2: R50.2 SB9.2 U7.69(PB10)
NetR53_2: R53.2 ; port SAI1_SDA
NetR54_2: R54.2 ; port LED1
NetR56_2: R56.2 SB12.2 SB13.2 U7.47(PB1)
NetR62_2: R62.2 SB14.2 SB15.2 U7.46(PB0)
NetR66_2: R66.2 SB18.2 SB19.2 U7.43(PA7)
NetR68_2: R68.2 SB20.2 SB21.2 U7.42(PA6)
NetR71_2: SB8.1 ; port QSPI_CS
NetR78_1: R78.1 SB22.2 U7.37(PA3)
NetR81_2: R81.2 SB31.2 U7.36(PA2)
NetR82_2: R82.2 SB32.2 U7.35(PA1)
NetR103_1: R103.1 SB26.1 U7.1(PE2)
NetR104_1: R104.1 U7.2(PE3) ; port TRACE_D0
NetR156_2: SB40.2 ; port TRACE_D1
NetSB9_1: SB9.1 ; port QSPI_CLK
NetSB12_1: SB12.1 ; port QSPI_D0
NetSB14_1: SB14.1 ; port QSPI_D1
NetSB18_1: SB18.1 ; port QSPI_D2
NetSB21_1: SB21.1 ; port QSPI_D3

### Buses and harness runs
bus A[20..22] = port A[20..22]
bus D[0..15] = port D[0..15]
bus LCDCOM[0..3] = port LCDCOM[0..3]
bus LCDSEG[0..17] = port LCDSEG[0..17]
bus LCDSEG[28..39] = port LCDSEG[28..39]
bus PA[0..15] = port PA[0..15]
bus PB[0..15] = port PB[0..15]
bus PD[0..15] = port PD[0..15]
bus PE[0..15] = port PE[0..15]

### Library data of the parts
R38 R48 R50 R53 R56 R62 R66 R68 R81 R82 R103 R104 = Res1: Resistor; Value: 1K; Ordered by: Subcon; ECCN_US/EU: NA
R39 R54 R69 R78 R83-R86 R100-R102 = res1: Resistor; Value: 1K; Ordered by: Subcon; ECCN_US/EU: NA
SB3 SB6 SB8-SB15 SB18-SB22 SB26 SB31 SB32 SB35 SB38-SB40 = Circuit Breaker: Ordered by: Subcon; Comments: Solder bridge; Fitted: NO; ECCN_US/EU: NA
U7 = STM32L476_TQFP144: Manuf_Part_1: STM32L476ZGT6U cut1.3; Ordered by: ST; ECCN_US/EU: 3A991A2/NEC; Assembly: MCU; Ref St: 9175195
